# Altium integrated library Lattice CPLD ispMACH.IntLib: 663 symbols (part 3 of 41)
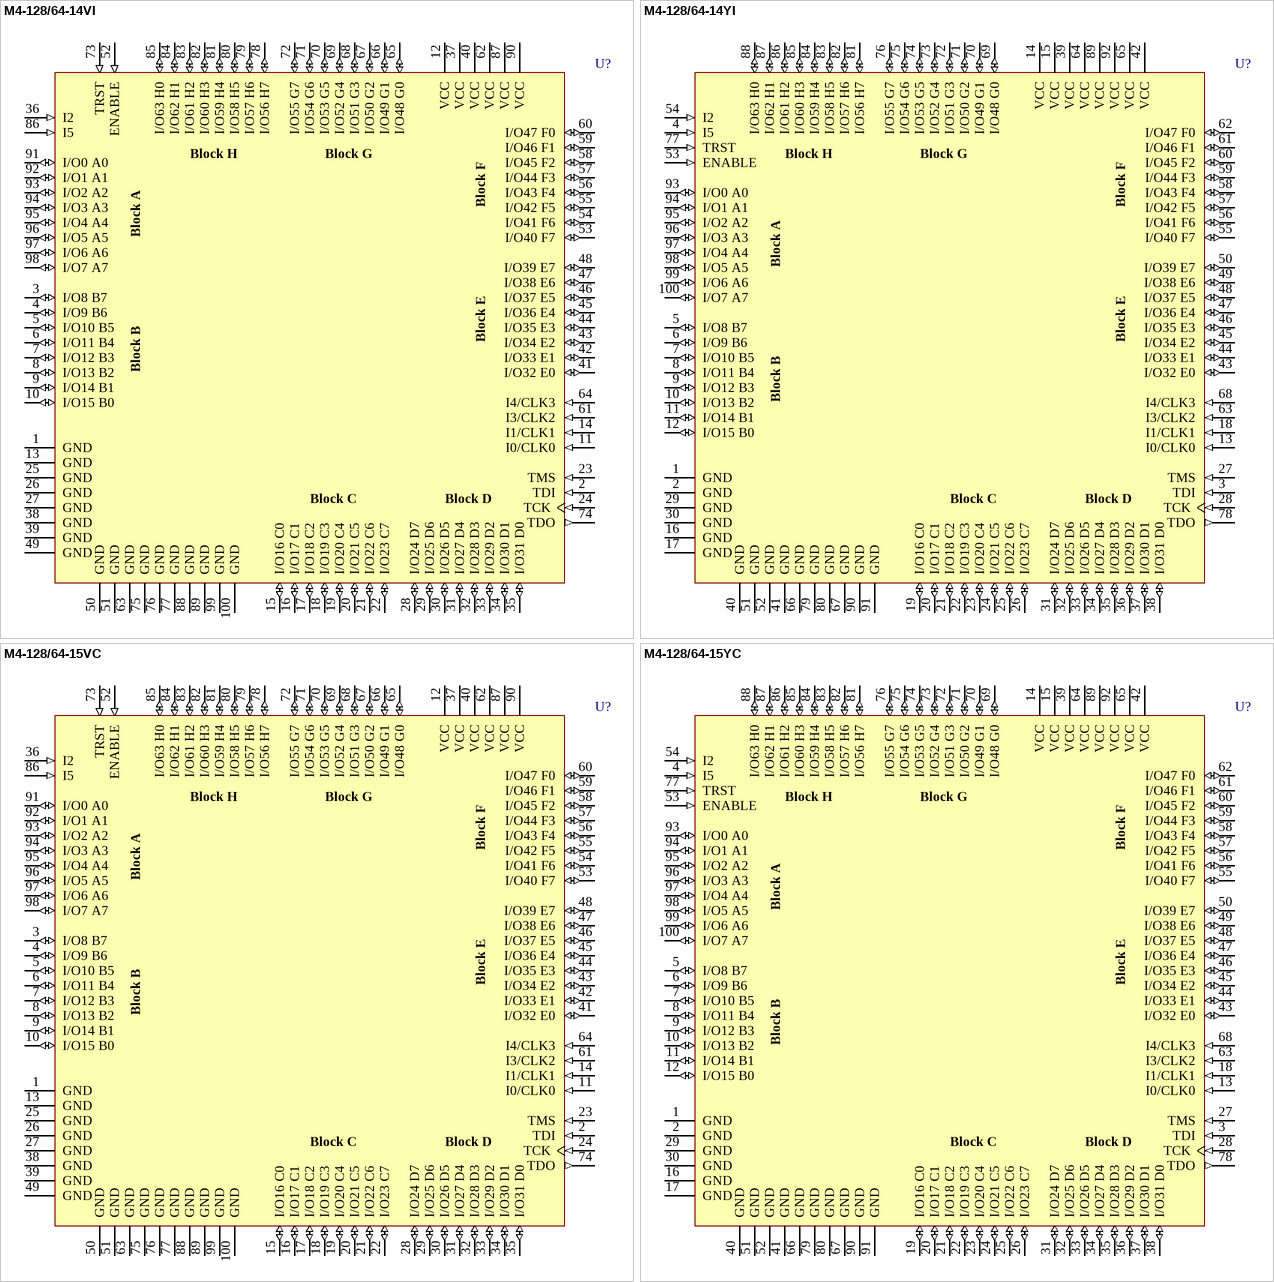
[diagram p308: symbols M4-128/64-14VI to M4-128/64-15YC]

## M4-128/64-15VC
designator U?
High-Performance EE CMOS In-System Programmable Logic
footprint TQFP100_N (Thin QFP, 100-Leads, Body 14x14mm, Pitch 0.5mm, IPC Medium Density)
footprint TQFP100_L (Thin QFP, 100-Leads, Body 14x14mm, Pitch 0.5mm, IPC High Density)
footprint TQFP100_M (Thin QFP, 100-Leads, Body 14x14mm, Pitch 0.5mm, IPC Low Density)
3D model M4-TQFP100 (100-Pin Thin Quad Flat Pack (TQFP100))
pins: 1 GND (power), 2 TDI (in), 3 I/O8 B7 (io), 4 I/O9 B6 (io), 5 I/O10 B5 (io), 6 I/O11 B4 (io), 7 I/O12 B3 (io), 8 I/O13 B2 (io), 9 I/O14 B1 (io), 10 I/O15 B0 (io), 11 I0/CLK0 (in), 12 VCC (power), 13 GND (power), 14 I1/CLK1 (in), 15 I/O16 C0 (io), 16 I/O17 C1 (io), 17 I/O18 C2 (io), 18 I/O19 C3 (io), 19 I/O20 C4 (io), 20 I/O21 C5 (io), 21 I/O22 C6 (io), 22 I/O23 C7 (io), 23 TMS (in), 24 TCK (in), 25 GND (power), 26 GND (power), 27 GND (power), 28 I/O24 D7 (io), 29 I/O25 D6 (io), 30 I/O26 D5 (io), 31 I/O27 D4 (io), 32 I/O28 D3 (io), 33 I/O29 D2 (io), 34 I/O30 D1 (io), 35 I/O31 D0 (io), 36 I2 (in), 37 VCC (power), 38 GND (power), 39 GND (power), 40 VCC (power), 41 I/O32 E0 (io), 42 I/O33 E1 (io), 43 I/O34 E2 (io), 44 I/O35 E3 (io), 45 I/O36 E4 (io), 46 I/O37 E5 (io), 47 I/O38 E6 (io), 48 I/O39 E7 (io), 49 GND (power), 50 GND (power), 51 GND (power), 52 ENABLE (in), 53 I/O40 F7 (io), 54 I/O41 F6 (io), 55 I/O42 F5 (io), 56 I/O43 F4 (io), 57 I/O44 F3 (io), 58 I/O45 F2 (io), 59 I/O46 F1 (io), 60 I/O47 F0 (io), 61 I3/CLK2 (in), 62 VCC (power), 63 GND (power), 64 I4/CLK3 (in), 65 I/O48 G0 (io), 66 I/O49 G1 (io), 67 I/O50 G2 (io), 68 I/O51 G3 (io), 69 I/O52 G4 (io), 70 I/O53 G5 (io), 71 I/O54 G6 (io), 72 I/O55 G7 (io), 73 TRST (in), 74 TDO (out), 75 GND (power), 76 GND (power), 77 GND (power), 78 I/O56 H7 (io), 79 I/O57 H6 (io), 80 I/O58 H5 (io), 81 I/O59 H4 (io), 82 I/O60 H3 (io), 83 I/O61 H2 (io), 84 I/O62 H1 (io), 85 I/O63 H0 (io), 86 I5 (in), 87 VCC (power), 88 GND (power), 89 GND (power), 90 VCC (power), 91 I/O0 A0 (io), 92 I/O1 A1 (io), 93 I/O2 A2 (io), 94 I/O3 A3 (io), 95 I/O4 A4 (io), 96 I/O5 A5 (io), 97 I/O6 A6 (io), 98 I/O7 A7 (io), 99 GND (power), 100 GND (power)

## M4-128/64-15YC
designator U?
High-Performance EE CMOS In-System Programmable Logic
footprint PQFP100_N (QFP, 100-Leads, Body 20x14mm, Pitch 0.65mm, IPC Medium Density)
footprint PQFP100_L (QFP, 100-Leads, Body 20x14mm, Pitch 0.65mm, IPC High Density)
footprint PQFP100_M (QFP, 100-Leads, Body 20x14mm, Pitch 0.65mm, IPC Low Density)
3D model PQFP-100 (100-Pin Quad Flat Pack Rectangular 0.65 mm Pitch)
pins: 1 GND (power), 2 GND (power), 3 TDI (in), 4 I5 (in), 5 I/O8 B7 (io), 6 I/O9 B6 (io), 7 I/O10 B5 (io), 8 I/O11 B4 (io), 9 I/O12 B3 (io), 10 I/O13 B2 (io), 11 I/O14 B1 (io), 12 I/O15 B0 (io), 13 I0/CLK0 (in), 14 VCC (power), 15 VCC (power), 16 GND (power), 17 GND (power), 18 I1/CLK1 (in), 19 I/O16 C0 (io), 20 I/O17 C1 (io), 21 I/O18 C2 (io), 22 I/O19 C3 (io), 23 I/O20 C4 (io), 24 I/O21 C5 (io), 25 I/O22 C6 (io), 26 I/O23 C7 (io), 27 TMS (in), 28 TCK (in), 29 GND (power), 30 GND (power), 31 I/O24 D7 (io), 32 I/O25 D6 (io), 33 I/O26 D5 (io), 34 I/O27 D4 (io), 35 I/O28 D3 (io), 36 I/O29 D2 (io), 37 I/O30 D1 (io), 38 I/O31 D0 (io), 39 VCC (power), 40 GND (power), 41 GND (power), 42 VCC (power), 43 I/O32 E0 (io), 44 I/O33 E1 (io), 45 I/O34 E2 (io), 46 I/O35 E3 (io), 47 I/O36 E4 (io), 48 I/O37 E5 (io), 49 I/O38 E6 (io), 50 I/O39 E7 (io), 51 GND (power), 52 GND (power), 53 ENABLE (in), 54 I2 (in), 55 I/O40 F7 (io), 56 I/O41 F6 (io), 57 I/O42 F5 (io), 58 I/O43 F4 (io), 59 I/O44 F3 (io), 60 I/O45 F2 (io), 61 I/O46 F1 (io), 62 I/O47 F0 (io), 63 I3/CLK2 (in), 64 VCC (power), 65 VCC (power), 66 GND (power), 67 GND (power), 68 I4/CLK3 (in), 69 I/O48 G0 (io), 70 I/O49 G1 (io), 71 I/O50 G2 (io), 72 I/O51 G3 (io), 73 I/O52 G4 (io), 74 I/O53 G5 (io), 75 I/O54 G6 (io), 76 I/O55 G7 (io), 77 TRST (in), 78 TDO (out), 79 GND (power), 80 GND (power), 81 I/O56 H7 (io), 82 I/O57 H6 (io), 83 I/O58 H5 (io), 84 I/O59 H4 (io), 85 I/O60 H3 (io), 86 I/O61 H2 (io), 87 I/O62 H1 (io), 88 I/O63 H0 (io), 89 VCC (power), 90 GND (power), 91 GND (power), 92 VCC (power), 93 I/O0 A0 (io), 94 I/O1 A1 (io), 95 I/O2 A2 (io), 96 I/O3 A3 (io), 97 I/O4 A4 (io), 98 I/O5 A5 (io), 99 I/O6 A6 (io), 100 I/O7 A7 (io)

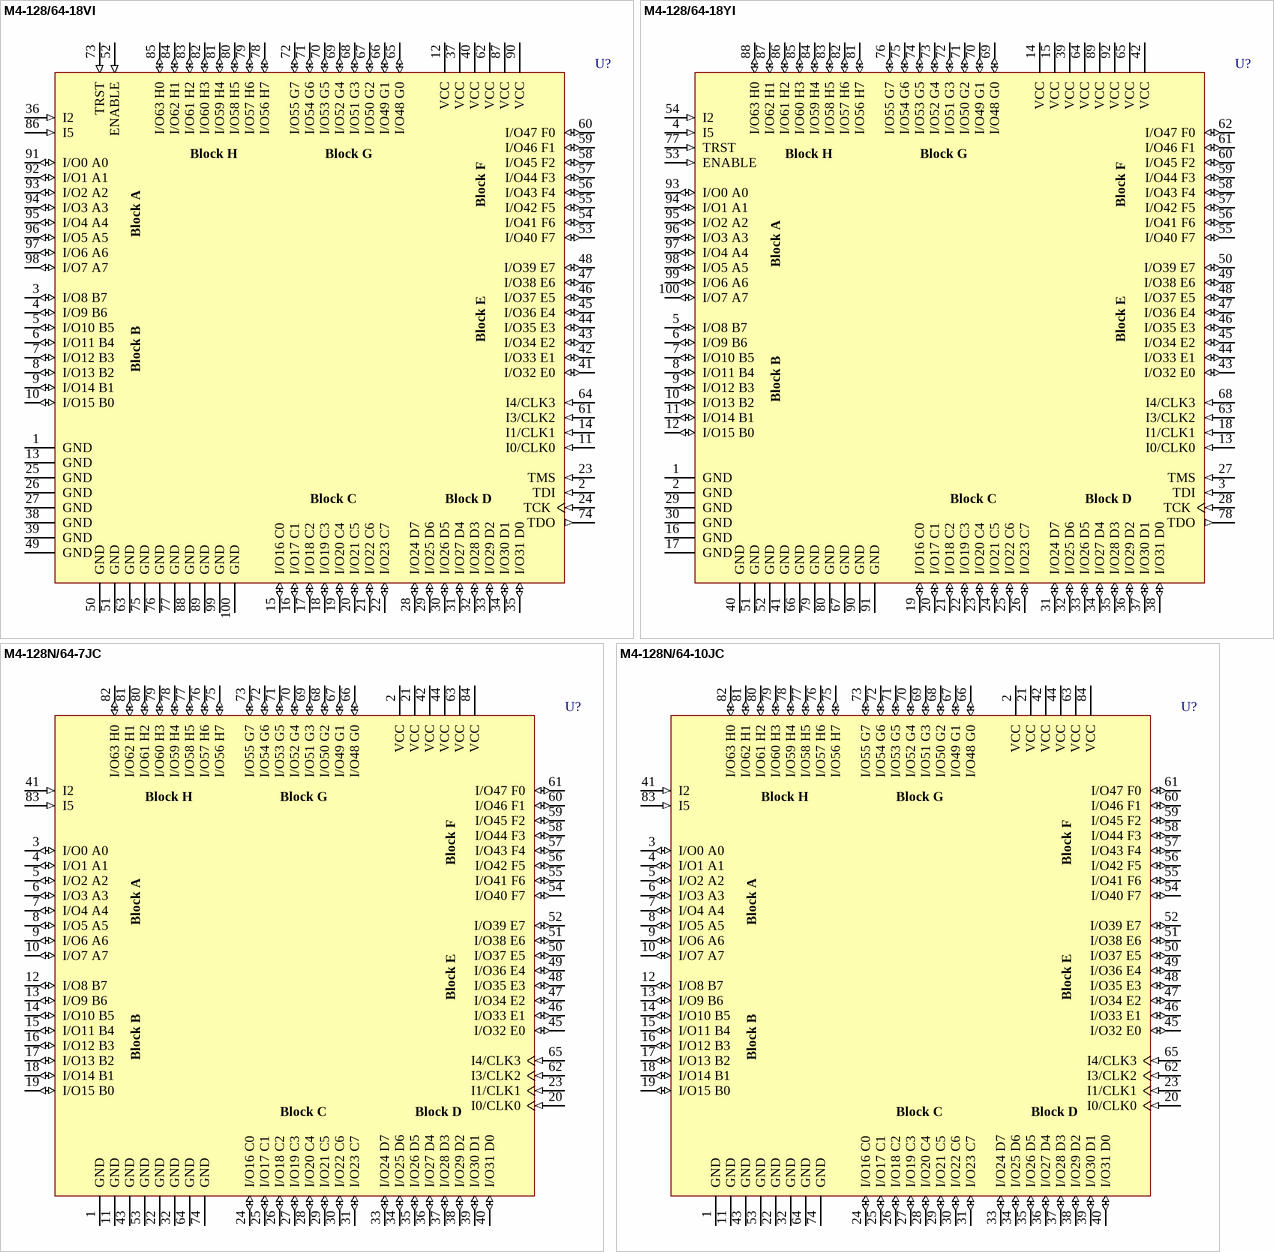
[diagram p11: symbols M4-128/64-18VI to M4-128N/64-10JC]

## M4-128/64-18VI
designator U?
High-Performance EE CMOS In-System Programmable Logic
footprint TQFP100_N (Thin QFP, 100-Leads, Body 14x14mm, Pitch 0.5mm, IPC Medium Density)
footprint TQFP100_L (Thin QFP, 100-Leads, Body 14x14mm, Pitch 0.5mm, IPC High Density)
footprint TQFP100_M (Thin QFP, 100-Leads, Body 14x14mm, Pitch 0.5mm, IPC Low Density)
3D model M4-TQFP100 (100-Pin Thin Quad Flat Pack (TQFP100))
pins: 1 GND (power), 2 TDI (in), 3 I/O8 B7 (io), 4 I/O9 B6 (io), 5 I/O10 B5 (io), 6 I/O11 B4 (io), 7 I/O12 B3 (io), 8 I/O13 B2 (io), 9 I/O14 B1 (io), 10 I/O15 B0 (io), 11 I0/CLK0 (in), 12 VCC (power), 13 GND (power), 14 I1/CLK1 (in), 15 I/O16 C0 (io), 16 I/O17 C1 (io), 17 I/O18 C2 (io), 18 I/O19 C3 (io), 19 I/O20 C4 (io), 20 I/O21 C5 (io), 21 I/O22 C6 (io), 22 I/O23 C7 (io), 23 TMS (in), 24 TCK (in), 25 GND (power), 26 GND (power), 27 GND (power), 28 I/O24 D7 (io), 29 I/O25 D6 (io), 30 I/O26 D5 (io), 31 I/O27 D4 (io), 32 I/O28 D3 (io), 33 I/O29 D2 (io), 34 I/O30 D1 (io), 35 I/O31 D0 (io), 36 I2 (in), 37 VCC (power), 38 GND (power), 39 GND (power), 40 VCC (power), 41 I/O32 E0 (io), 42 I/O33 E1 (io), 43 I/O34 E2 (io), 44 I/O35 E3 (io), 45 I/O36 E4 (io), 46 I/O37 E5 (io), 47 I/O38 E6 (io), 48 I/O39 E7 (io), 49 GND (power), 50 GND (power), 51 GND (power), 52 ENABLE (in), 53 I/O40 F7 (io), 54 I/O41 F6 (io), 55 I/O42 F5 (io), 56 I/O43 F4 (io), 57 I/O44 F3 (io), 58 I/O45 F2 (io), 59 I/O46 F1 (io), 60 I/O47 F0 (io), 61 I3/CLK2 (in), 62 VCC (power), 63 GND (power), 64 I4/CLK3 (in), 65 I/O48 G0 (io), 66 I/O49 G1 (io), 67 I/O50 G2 (io), 68 I/O51 G3 (io), 69 I/O52 G4 (io), 70 I/O53 G5 (io), 71 I/O54 G6 (io), 72 I/O55 G7 (io), 73 TRST (in), 74 TDO (out), 75 GND (power), 76 GND (power), 77 GND (power), 78 I/O56 H7 (io), 79 I/O57 H6 (io), 80 I/O58 H5 (io), 81 I/O59 H4 (io), 82 I/O60 H3 (io), 83 I/O61 H2 (io), 84 I/O62 H1 (io), 85 I/O63 H0 (io), 86 I5 (in), 87 VCC (power), 88 GND (power), 89 GND (power), 90 VCC (power), 91 I/O0 A0 (io), 92 I/O1 A1 (io), 93 I/O2 A2 (io), 94 I/O3 A3 (io), 95 I/O4 A4 (io), 96 I/O5 A5 (io), 97 I/O6 A6 (io), 98 I/O7 A7 (io), 99 GND (power), 100 GND (power)

## M4-128/64-18YI
designator U?
High-Performance EE CMOS In-System Programmable Logic
footprint PQFP100_N (QFP, 100-Leads, Body 20x14mm, Pitch 0.65mm, IPC Medium Density)
footprint PQFP100_L (QFP, 100-Leads, Body 20x14mm, Pitch 0.65mm, IPC High Density)
footprint PQFP100_M (QFP, 100-Leads, Body 20x14mm, Pitch 0.65mm, IPC Low Density)
3D model PQFP-100 (100-Pin Quad Flat Pack Rectangular 0.65 mm Pitch)
pins: 1 GND (power), 2 GND (power), 3 TDI (in), 4 I5 (in), 5 I/O8 B7 (io), 6 I/O9 B6 (io), 7 I/O10 B5 (io), 8 I/O11 B4 (io), 9 I/O12 B3 (io), 10 I/O13 B2 (io), 11 I/O14 B1 (io), 12 I/O15 B0 (io), 13 I0/CLK0 (in), 14 VCC (power), 15 VCC (power), 16 GND (power), 17 GND (power), 18 I1/CLK1 (in), 19 I/O16 C0 (io), 20 I/O17 C1 (io), 21 I/O18 C2 (io), 22 I/O19 C3 (io), 23 I/O20 C4 (io), 24 I/O21 C5 (io), 25 I/O22 C6 (io), 26 I/O23 C7 (io), 27 TMS (in), 28 TCK (in), 29 GND (power), 30 GND (power), 31 I/O24 D7 (io), 32 I/O25 D6 (io), 33 I/O26 D5 (io), 34 I/O27 D4 (io), 35 I/O28 D3 (io), 36 I/O29 D2 (io), 37 I/O30 D1 (io), 38 I/O31 D0 (io), 39 VCC (power), 40 GND (power), 41 GND (power), 42 VCC (power), 43 I/O32 E0 (io), 44 I/O33 E1 (io), 45 I/O34 E2 (io), 46 I/O35 E3 (io), 47 I/O36 E4 (io), 48 I/O37 E5 (io), 49 I/O38 E6 (io), 50 I/O39 E7 (io), 51 GND (power), 52 GND (power), 53 ENABLE (in), 54 I2 (in), 55 I/O40 F7 (io), 56 I/O41 F6 (io), 57 I/O42 F5 (io), 58 I/O43 F4 (io), 59 I/O44 F3 (io), 60 I/O45 F2 (io), 61 I/O46 F1 (io), 62 I/O47 F0 (io), 63 I3/CLK2 (in), 64 VCC (power), 65 VCC (power), 66 GND (power), 67 GND (power), 68 I4/CLK3 (in), 69 I/O48 G0 (io), 70 I/O49 G1 (io), 71 I/O50 G2 (io), 72 I/O51 G3 (io), 73 I/O52 G4 (io), 74 I/O53 G5 (io), 75 I/O54 G6 (io), 76 I/O55 G7 (io), 77 TRST (in), 78 TDO (out), 79 GND (power), 80 GND (power), 81 I/O56 H7 (io), 82 I/O57 H6 (io), 83 I/O58 H5 (io), 84 I/O59 H4 (io), 85 I/O60 H3 (io), 86 I/O61 H2 (io), 87 I/O62 H1 (io), 88 I/O63 H0 (io), 89 VCC (power), 90 GND (power), 91 GND (power), 92 VCC (power), 93 I/O0 A0 (io), 94 I/O1 A1 (io), 95 I/O2 A2 (io), 96 I/O3 A3 (io), 97 I/O4 A4 (io), 98 I/O5 A5 (io), 99 I/O6 A6 (io), 100 I/O7 A7 (io)

## M4-128N/64-7JC
designator U?
High-Performance EE CMOS In-System Programmable Logic
footprint PLCC84_N (Leaded Chip Carrier, 84-Leads, Body 29.3x29.3mm, Pitch 1.27mm, IPC Medium Density)
footprint PLCC84_L (Leaded Chip Carrier, 84-Leads, Body 29.3x29.3mm, Pitch 1.27mm, IPC High Density)
footprint PLCC84_M (Leaded Chip Carrier, 84-Leads, Body 29.3x29.3mm, Pitch 1.27mm, IPC Low Density)
3D model M4-PLCC84 (84-Pin Leaded Chip Carrier 1.27 mm Pitch)
pins: 1 GND (power), 2 VCC (power), 3 I/O0 A0 (io), 4 I/O1 A1 (io), 5 I/O2 A2 (io), 6 I/O3 A3 (io), 7 I/O4 A4 (io), 8 I/O5 A5 (io), 9 I/O6 A6 (io), 10 I/O7 A7 (io), 11 GND (power), 12 I/O8 B7 (io), 13 I/O9 B6 (io), 14 I/O10 B5 (io), 15 I/O11 B4 (io), 16 I/O12 B3 (io), 17 I/O13 B2 (io), 18 I/O14 B1 (io), 19 I/O15 B0 (io), 20 I0/CLK0 (in), 21 VCC (power), 22 GND (power), 23 I1/CLK1 (in), 24 I/O16 C0 (io), 25 I/O17 C1 (io), 26 I/O18 C2 (io), 27 I/O19 C3 (io), 28 I/O20 C4 (io), 29 I/O21 C5 (io), 30 I/O22 C6 (io), 31 I/O23 C7 (io), 32 GND (power), 33 I/O24 D7 (io), 34 I/O25 D6 (io), 35 I/O26 D5 (io), 36 I/O27 D4 (io), 37 I/O28 D3 (io), 38 I/O29 D2 (io), 39 I/O30 D1 (io), 40 I/O31 D0 (io), 41 I2 (in), 42 VCC (power), 43 GND (power), 44 VCC (power), 45 I/O32 E0 (io), 46 I/O33 E1 (io), 47 I/O34 E2 (io), 48 I/O35 E3 (io), 49 I/O36 E4 (io), 50 I/O37 E5 (io), 51 I/O38 E6 (io), 52 I/O39 E7 (io), 53 GND (power), 54 I/O40 F7 (io), 55 I/O41 F6 (io), 56 I/O42 F5 (io), 57 I/O43 F4 (io), 58 I/O44 F3 (io), 59 I/O45 F2 (io), 60 I/O46 F1 (io), 61 I/O47 F0 (io), 62 I3/CLK2 (in), 63 VCC (power), 64 GND (power), 65 I4/CLK3 (in), 66 I/O48 G0 (io), 67 I/O49 G1 (io), 68 I/O50 G2 (io), 69 I/O51 G3 (io), 70 I/O52 G4 (io), 71 I/O53 G5 (io), 72 I/O54 G6 (io), 73 I/O55 G7 (io), 74 GND (power), 75 I/O56 H7 (io), 76 I/O57 H6 (io), 77 I/O58 H5 (io), 78 I/O59 H4 (io), 79 I/O60 H3 (io), 80 I/O61 H2 (io), 81 I/O62 H1 (io), 82 I/O63 H0 (io), 83 I5 (in), 84 VCC (power)

## M4-128N/64-10JC
designator U?
High-Performance EE CMOS In-System Programmable Logic
footprint PLCC84_N (Leaded Chip Carrier, 84-Leads, Body 29.3x29.3mm, Pitch 1.27mm, IPC Medium Density)
footprint PLCC84_L (Leaded Chip Carrier, 84-Leads, Body 29.3x29.3mm, Pitch 1.27mm, IPC High Density)
footprint PLCC84_M (Leaded Chip Carrier, 84-Leads, Body 29.3x29.3mm, Pitch 1.27mm, IPC Low Density)
3D model M4-PLCC84 (84-Pin Leaded Chip Carrier 1.27 mm Pitch)
pins: 1 GND (power), 2 VCC (power), 3 I/O0 A0 (io), 4 I/O1 A1 (io), 5 I/O2 A2 (io), 6 I/O3 A3 (io), 7 I/O4 A4 (io), 8 I/O5 A5 (io), 9 I/O6 A6 (io), 10 I/O7 A7 (io), 11 GND (power), 12 I/O8 B7 (io), 13 I/O9 B6 (io), 14 I/O10 B5 (io), 15 I/O11 B4 (io), 16 I/O12 B3 (io), 17 I/O13 B2 (io), 18 I/O14 B1 (io), 19 I/O15 B0 (io), 20 I0/CLK0 (in), 21 VCC (power), 22 GND (power), 23 I1/CLK1 (in), 24 I/O16 C0 (io), 25 I/O17 C1 (io), 26 I/O18 C2 (io), 27 I/O19 C3 (io), 28 I/O20 C4 (io), 29 I/O21 C5 (io), 30 I/O22 C6 (io), 31 I/O23 C7 (io), 32 GND (power), 33 I/O24 D7 (io), 34 I/O25 D6 (io), 35 I/O26 D5 (io), 36 I/O27 D4 (io), 37 I/O28 D3 (io), 38 I/O29 D2 (io), 39 I/O30 D1 (io), 40 I/O31 D0 (io), 41 I2 (in), 42 VCC (power), 43 GND (power), 44 VCC (power), 45 I/O32 E0 (io), 46 I/O33 E1 (io), 47 I/O34 E2 (io), 48 I/O35 E3 (io), 49 I/O36 E4 (io), 50 I/O37 E5 (io), 51 I/O38 E6 (io), 52 I/O39 E7 (io), 53 GND (power), 54 I/O40 F7 (io), 55 I/O41 F6 (io), 56 I/O42 F5 (io), 57 I/O43 F4 (io), 58 I/O44 F3 (io), 59 I/O45 F2 (io), 60 I/O46 F1 (io), 61 I/O47 F0 (io), 62 I3/CLK2 (in), 63 VCC (power), 64 GND (power), 65 I4/CLK3 (in), 66 I/O48 G0 (io), 67 I/O49 G1 (io), 68 I/O50 G2 (io), 69 I/O51 G3 (io), 70 I/O52 G4 (io), 71 I/O53 G5 (io), 72 I/O54 G6 (io), 73 I/O55 G7 (io), 74 GND (power), 75 I/O56 H7 (io), 76 I/O57 H6 (io), 77 I/O58 H5 (io), 78 I/O59 H4 (io), 79 I/O60 H3 (io), 80 I/O61 H2 (io), 81 I/O62 H1 (io), 82 I/O63 H0 (io), 83 I5 (in), 84 VCC (power)

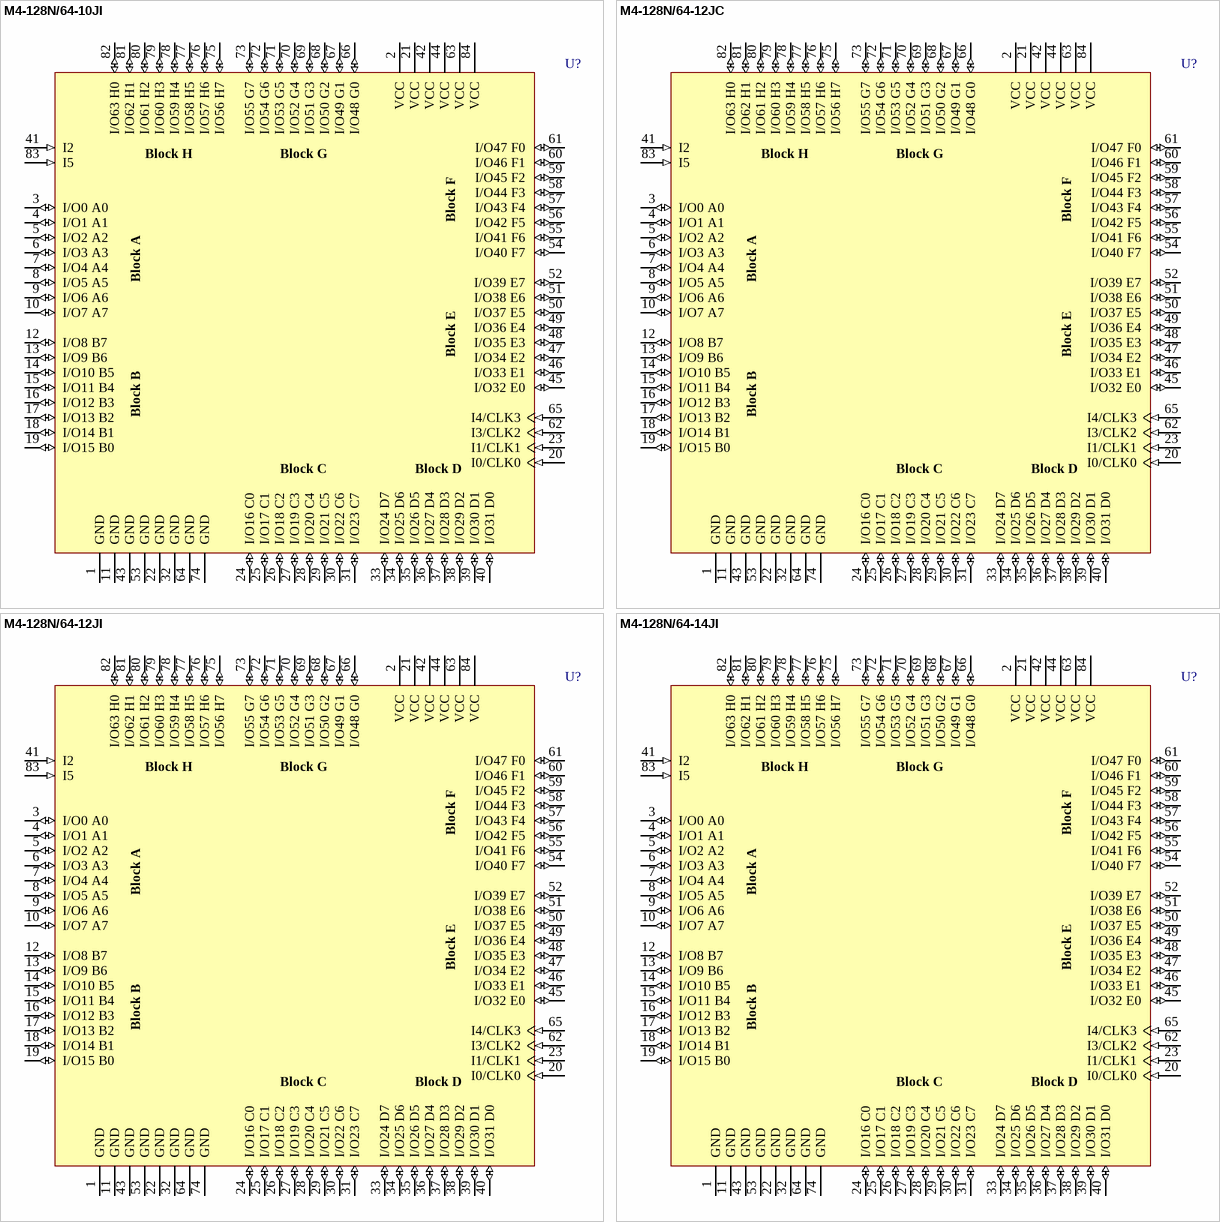
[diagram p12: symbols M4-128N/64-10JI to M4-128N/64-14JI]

## M4-128N/64-10JI
designator U?
High-Performance EE CMOS In-System Programmable Logic
footprint PLCC84_N (Leaded Chip Carrier, 84-Leads, Body 29.3x29.3mm, Pitch 1.27mm, IPC Medium Density)
footprint PLCC84_L (Leaded Chip Carrier, 84-Leads, Body 29.3x29.3mm, Pitch 1.27mm, IPC High Density)
footprint PLCC84_M (Leaded Chip Carrier, 84-Leads, Body 29.3x29.3mm, Pitch 1.27mm, IPC Low Density)
3D model M4-PLCC84 (84-Pin Leaded Chip Carrier 1.27 mm Pitch)
pins: 1 GND (power), 2 VCC (power), 3 I/O0 A0 (io), 4 I/O1 A1 (io), 5 I/O2 A2 (io), 6 I/O3 A3 (io), 7 I/O4 A4 (io), 8 I/O5 A5 (io), 9 I/O6 A6 (io), 10 I/O7 A7 (io), 11 GND (power), 12 I/O8 B7 (io), 13 I/O9 B6 (io), 14 I/O10 B5 (io), 15 I/O11 B4 (io), 16 I/O12 B3 (io), 17 I/O13 B2 (io), 18 I/O14 B1 (io), 19 I/O15 B0 (io), 20 I0/CLK0 (in), 21 VCC (power), 22 GND (power), 23 I1/CLK1 (in), 24 I/O16 C0 (io), 25 I/O17 C1 (io), 26 I/O18 C2 (io), 27 I/O19 C3 (io), 28 I/O20 C4 (io), 29 I/O21 C5 (io), 30 I/O22 C6 (io), 31 I/O23 C7 (io), 32 GND (power), 33 I/O24 D7 (io), 34 I/O25 D6 (io), 35 I/O26 D5 (io), 36 I/O27 D4 (io), 37 I/O28 D3 (io), 38 I/O29 D2 (io), 39 I/O30 D1 (io), 40 I/O31 D0 (io), 41 I2 (in), 42 VCC (power), 43 GND (power), 44 VCC (power), 45 I/O32 E0 (io), 46 I/O33 E1 (io), 47 I/O34 E2 (io), 48 I/O35 E3 (io), 49 I/O36 E4 (io), 50 I/O37 E5 (io), 51 I/O38 E6 (io), 52 I/O39 E7 (io), 53 GND (power), 54 I/O40 F7 (io), 55 I/O41 F6 (io), 56 I/O42 F5 (io), 57 I/O43 F4 (io), 58 I/O44 F3 (io), 59 I/O45 F2 (io), 60 I/O46 F1 (io), 61 I/O47 F0 (io), 62 I3/CLK2 (in), 63 VCC (power), 64 GND (power), 65 I4/CLK3 (in), 66 I/O48 G0 (io), 67 I/O49 G1 (io), 68 I/O50 G2 (io), 69 I/O51 G3 (io), 70 I/O52 G4 (io), 71 I/O53 G5 (io), 72 I/O54 G6 (io), 73 I/O55 G7 (io), 74 GND (power), 75 I/O56 H7 (io), 76 I/O57 H6 (io), 77 I/O58 H5 (io), 78 I/O59 H4 (io), 79 I/O60 H3 (io), 80 I/O61 H2 (io), 81 I/O62 H1 (io), 82 I/O63 H0 (io), 83 I5 (in), 84 VCC (power)

## M4-128N/64-12JC
designator U?
High-Performance EE CMOS In-System Programmable Logic
footprint PLCC84_N (Leaded Chip Carrier, 84-Leads, Body 29.3x29.3mm, Pitch 1.27mm, IPC Medium Density)
footprint PLCC84_L (Leaded Chip Carrier, 84-Leads, Body 29.3x29.3mm, Pitch 1.27mm, IPC High Density)
footprint PLCC84_M (Leaded Chip Carrier, 84-Leads, Body 29.3x29.3mm, Pitch 1.27mm, IPC Low Density)
3D model M4-PLCC84 (84-Pin Leaded Chip Carrier 1.27 mm Pitch)
pins: 1 GND (power), 2 VCC (power), 3 I/O0 A0 (io), 4 I/O1 A1 (io), 5 I/O2 A2 (io), 6 I/O3 A3 (io), 7 I/O4 A4 (io), 8 I/O5 A5 (io), 9 I/O6 A6 (io), 10 I/O7 A7 (io), 11 GND (power), 12 I/O8 B7 (io), 13 I/O9 B6 (io), 14 I/O10 B5 (io), 15 I/O11 B4 (io), 16 I/O12 B3 (io), 17 I/O13 B2 (io), 18 I/O14 B1 (io), 19 I/O15 B0 (io), 20 I0/CLK0 (in), 21 VCC (power), 22 GND (power), 23 I1/CLK1 (in), 24 I/O16 C0 (io), 25 I/O17 C1 (io), 26 I/O18 C2 (io), 27 I/O19 C3 (io), 28 I/O20 C4 (io), 29 I/O21 C5 (io), 30 I/O22 C6 (io), 31 I/O23 C7 (io), 32 GND (power), 33 I/O24 D7 (io), 34 I/O25 D6 (io), 35 I/O26 D5 (io), 36 I/O27 D4 (io), 37 I/O28 D3 (io), 38 I/O29 D2 (io), 39 I/O30 D1 (io), 40 I/O31 D0 (io), 41 I2 (in), 42 VCC (power), 43 GND (power), 44 VCC (power), 45 I/O32 E0 (io), 46 I/O33 E1 (io), 47 I/O34 E2 (io), 48 I/O35 E3 (io), 49 I/O36 E4 (io), 50 I/O37 E5 (io), 51 I/O38 E6 (io), 52 I/O39 E7 (io), 53 GND (power), 54 I/O40 F7 (io), 55 I/O41 F6 (io), 56 I/O42 F5 (io), 57 I/O43 F4 (io), 58 I/O44 F3 (io), 59 I/O45 F2 (io), 60 I/O46 F1 (io), 61 I/O47 F0 (io), 62 I3/CLK2 (in), 63 VCC (power), 64 GND (power), 65 I4/CLK3 (in), 66 I/O48 G0 (io), 67 I/O49 G1 (io), 68 I/O50 G2 (io), 69 I/O51 G3 (io), 70 I/O52 G4 (io), 71 I/O53 G5 (io), 72 I/O54 G6 (io), 73 I/O55 G7 (io), 74 GND (power), 75 I/O56 H7 (io), 76 I/O57 H6 (io), 77 I/O58 H5 (io), 78 I/O59 H4 (io), 79 I/O60 H3 (io), 80 I/O61 H2 (io), 81 I/O62 H1 (io), 82 I/O63 H0 (io), 83 I5 (in), 84 VCC (power)

## M4-128N/64-12JI
designator U?
High-Performance EE CMOS In-System Programmable Logic
footprint PLCC84_N (Leaded Chip Carrier, 84-Leads, Body 29.3x29.3mm, Pitch 1.27mm, IPC Medium Density)
footprint PLCC84_L (Leaded Chip Carrier, 84-Leads, Body 29.3x29.3mm, Pitch 1.27mm, IPC High Density)
footprint PLCC84_M (Leaded Chip Carrier, 84-Leads, Body 29.3x29.3mm, Pitch 1.27mm, IPC Low Density)
3D model M4-PLCC84 (84-Pin Leaded Chip Carrier 1.27 mm Pitch)
pins: 1 GND (power), 2 VCC (power), 3 I/O0 A0 (io), 4 I/O1 A1 (io), 5 I/O2 A2 (io), 6 I/O3 A3 (io), 7 I/O4 A4 (io), 8 I/O5 A5 (io), 9 I/O6 A6 (io), 10 I/O7 A7 (io), 11 GND (power), 12 I/O8 B7 (io), 13 I/O9 B6 (io), 14 I/O10 B5 (io), 15 I/O11 B4 (io), 16 I/O12 B3 (io), 17 I/O13 B2 (io), 18 I/O14 B1 (io), 19 I/O15 B0 (io), 20 I0/CLK0 (in), 21 VCC (power), 22 GND (power), 23 I1/CLK1 (in), 24 I/O16 C0 (io), 25 I/O17 C1 (io), 26 I/O18 C2 (io), 27 I/O19 C3 (io), 28 I/O20 C4 (io), 29 I/O21 C5 (io), 30 I/O22 C6 (io), 31 I/O23 C7 (io), 32 GND (power), 33 I/O24 D7 (io), 34 I/O25 D6 (io), 35 I/O26 D5 (io), 36 I/O27 D4 (io), 37 I/O28 D3 (io), 38 I/O29 D2 (io), 39 I/O30 D1 (io), 40 I/O31 D0 (io), 41 I2 (in), 42 VCC (power), 43 GND (power), 44 VCC (power), 45 I/O32 E0 (io), 46 I/O33 E1 (io), 47 I/O34 E2 (io), 48 I/O35 E3 (io), 49 I/O36 E4 (io), 50 I/O37 E5 (io), 51 I/O38 E6 (io), 52 I/O39 E7 (io), 53 GND (power), 54 I/O40 F7 (io), 55 I/O41 F6 (io), 56 I/O42 F5 (io), 57 I/O43 F4 (io), 58 I/O44 F3 (io), 59 I/O45 F2 (io), 60 I/O46 F1 (io), 61 I/O47 F0 (io), 62 I3/CLK2 (in), 63 VCC (power), 64 GND (power), 65 I4/CLK3 (in), 66 I/O48 G0 (io), 67 I/O49 G1 (io), 68 I/O50 G2 (io), 69 I/O51 G3 (io), 70 I/O52 G4 (io), 71 I/O53 G5 (io), 72 I/O54 G6 (io), 73 I/O55 G7 (io), 74 GND (power), 75 I/O56 H7 (io), 76 I/O57 H6 (io), 77 I/O58 H5 (io), 78 I/O59 H4 (io), 79 I/O60 H3 (io), 80 I/O61 H2 (io), 81 I/O62 H1 (io), 82 I/O63 H0 (io), 83 I5 (in), 84 VCC (power)

## M4-128N/64-14JI
designator U?
High-Performance EE CMOS In-System Programmable Logic
footprint PLCC84_N (Leaded Chip Carrier, 84-Leads, Body 29.3x29.3mm, Pitch 1.27mm, IPC Medium Density)
footprint PLCC84_L (Leaded Chip Carrier, 84-Leads, Body 29.3x29.3mm, Pitch 1.27mm, IPC High Density)
footprint PLCC84_M (Leaded Chip Carrier, 84-Leads, Body 29.3x29.3mm, Pitch 1.27mm, IPC Low Density)
3D model M4-PLCC84 (84-Pin Leaded Chip Carrier 1.27 mm Pitch)
pins: 1 GND (power), 2 VCC (power), 3 I/O0 A0 (io), 4 I/O1 A1 (io), 5 I/O2 A2 (io), 6 I/O3 A3 (io), 7 I/O4 A4 (io), 8 I/O5 A5 (io), 9 I/O6 A6 (io), 10 I/O7 A7 (io), 11 GND (power), 12 I/O8 B7 (io), 13 I/O9 B6 (io), 14 I/O10 B5 (io), 15 I/O11 B4 (io), 16 I/O12 B3 (io), 17 I/O13 B2 (io), 18 I/O14 B1 (io), 19 I/O15 B0 (io), 20 I0/CLK0 (in), 21 VCC (power), 22 GND (power), 23 I1/CLK1 (in), 24 I/O16 C0 (io), 25 I/O17 C1 (io), 26 I/O18 C2 (io), 27 I/O19 C3 (io), 28 I/O20 C4 (io), 29 I/O21 C5 (io), 30 I/O22 C6 (io), 31 I/O23 C7 (io), 32 GND (power), 33 I/O24 D7 (io), 34 I/O25 D6 (io), 35 I/O26 D5 (io), 36 I/O27 D4 (io), 37 I/O28 D3 (io), 38 I/O29 D2 (io), 39 I/O30 D1 (io), 40 I/O31 D0 (io), 41 I2 (in), 42 VCC (power), 43 GND (power), 44 VCC (power), 45 I/O32 E0 (io), 46 I/O33 E1 (io), 47 I/O34 E2 (io), 48 I/O35 E3 (io), 49 I/O36 E4 (io), 50 I/O37 E5 (io), 51 I/O38 E6 (io), 52 I/O39 E7 (io), 53 GND (power), 54 I/O40 F7 (io), 55 I/O41 F6 (io), 56 I/O42 F5 (io), 57 I/O43 F4 (io), 58 I/O44 F3 (io), 59 I/O45 F2 (io), 60 I/O46 F1 (io), 61 I/O47 F0 (io), 62 I3/CLK2 (in), 63 VCC (power), 64 GND (power), 65 I4/CLK3 (in), 66 I/O48 G0 (io), 67 I/O49 G1 (io), 68 I/O50 G2 (io), 69 I/O51 G3 (io), 70 I/O52 G4 (io), 71 I/O53 G5 (io), 72 I/O54 G6 (io), 73 I/O55 G7 (io), 74 GND (power), 75 I/O56 H7 (io), 76 I/O57 H6 (io), 77 I/O58 H5 (io), 78 I/O59 H4 (io), 79 I/O60 H3 (io), 80 I/O61 H2 (io), 81 I/O62 H1 (io), 82 I/O63 H0 (io), 83 I5 (in), 84 VCC (power)

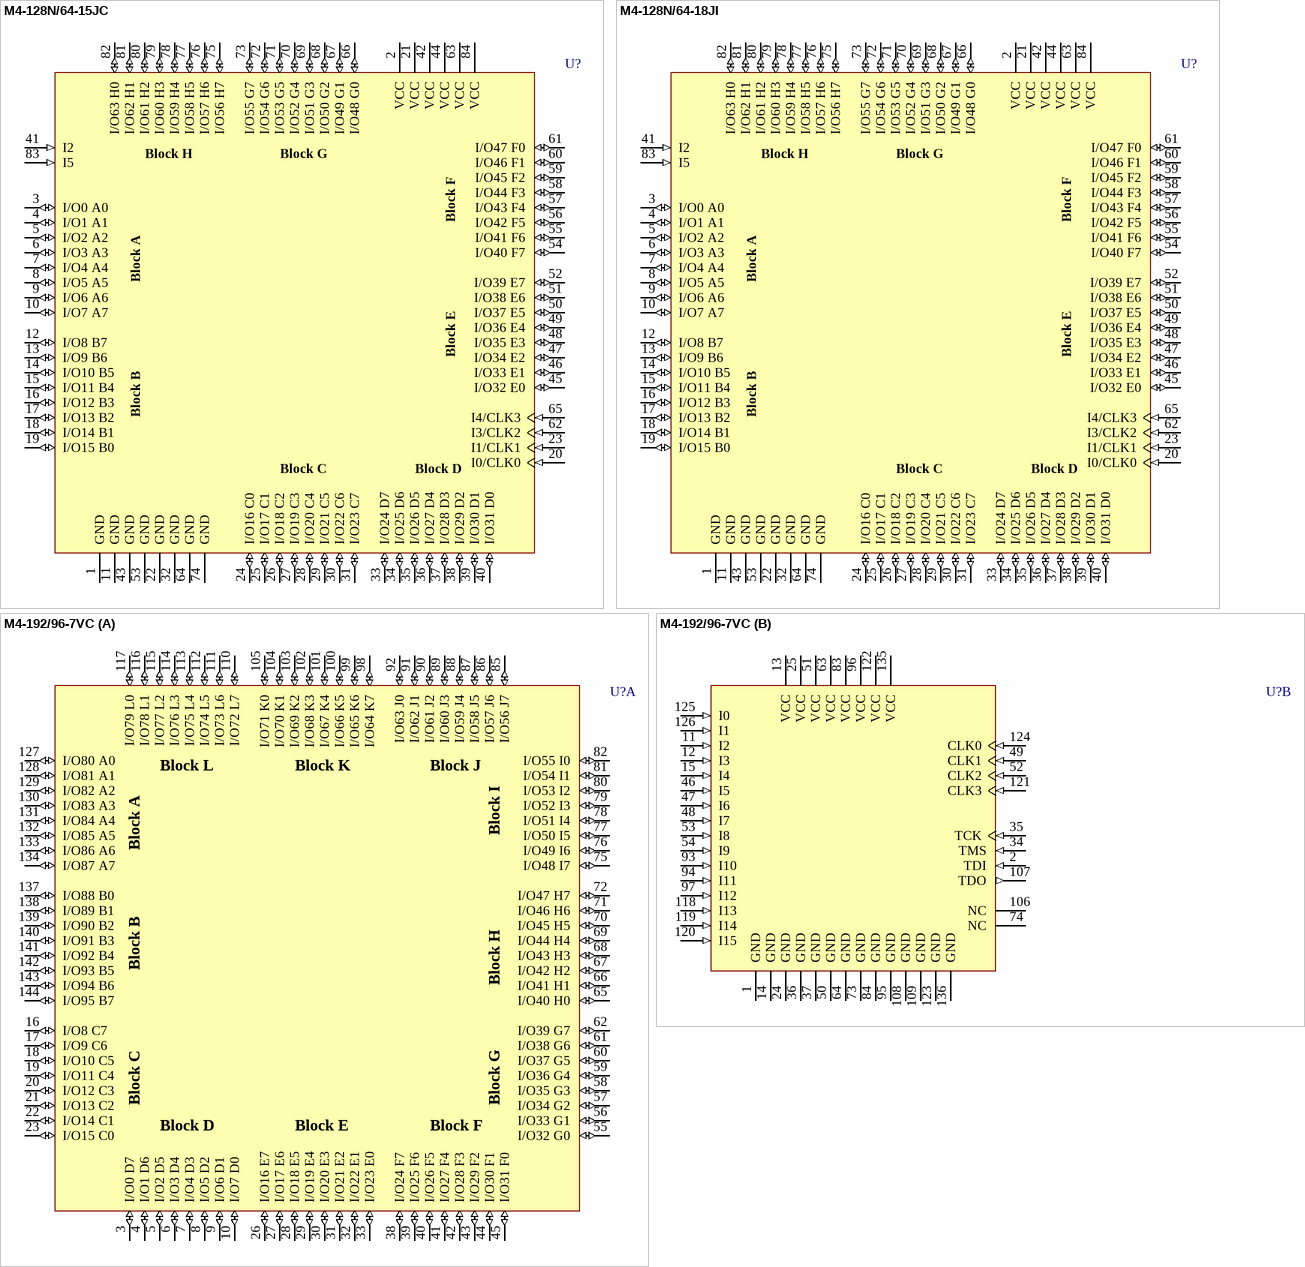
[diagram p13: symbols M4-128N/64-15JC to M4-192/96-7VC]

## M4-128N/64-15JC
designator U?
High-Performance EE CMOS In-System Programmable Logic
footprint PLCC84_N (Leaded Chip Carrier, 84-Leads, Body 29.3x29.3mm, Pitch 1.27mm, IPC Medium Density)
footprint PLCC84_L (Leaded Chip Carrier, 84-Leads, Body 29.3x29.3mm, Pitch 1.27mm, IPC High Density)
footprint PLCC84_M (Leaded Chip Carrier, 84-Leads, Body 29.3x29.3mm, Pitch 1.27mm, IPC Low Density)
3D model M4-PLCC84 (84-Pin Leaded Chip Carrier 1.27 mm Pitch)
pins: 1 GND (power), 2 VCC (power), 3 I/O0 A0 (io), 4 I/O1 A1 (io), 5 I/O2 A2 (io), 6 I/O3 A3 (io), 7 I/O4 A4 (io), 8 I/O5 A5 (io), 9 I/O6 A6 (io), 10 I/O7 A7 (io), 11 GND (power), 12 I/O8 B7 (io), 13 I/O9 B6 (io), 14 I/O10 B5 (io), 15 I/O11 B4 (io), 16 I/O12 B3 (io), 17 I/O13 B2 (io), 18 I/O14 B1 (io), 19 I/O15 B0 (io), 20 I0/CLK0 (in), 21 VCC (power), 22 GND (power), 23 I1/CLK1 (in), 24 I/O16 C0 (io), 25 I/O17 C1 (io), 26 I/O18 C2 (io), 27 I/O19 C3 (io), 28 I/O20 C4 (io), 29 I/O21 C5 (io), 30 I/O22 C6 (io), 31 I/O23 C7 (io), 32 GND (power), 33 I/O24 D7 (io), 34 I/O25 D6 (io), 35 I/O26 D5 (io), 36 I/O27 D4 (io), 37 I/O28 D3 (io), 38 I/O29 D2 (io), 39 I/O30 D1 (io), 40 I/O31 D0 (io), 41 I2 (in), 42 VCC (power), 43 GND (power), 44 VCC (power), 45 I/O32 E0 (io), 46 I/O33 E1 (io), 47 I/O34 E2 (io), 48 I/O35 E3 (io), 49 I/O36 E4 (io), 50 I/O37 E5 (io), 51 I/O38 E6 (io), 52 I/O39 E7 (io), 53 GND (power), 54 I/O40 F7 (io), 55 I/O41 F6 (io), 56 I/O42 F5 (io), 57 I/O43 F4 (io), 58 I/O44 F3 (io), 59 I/O45 F2 (io), 60 I/O46 F1 (io), 61 I/O47 F0 (io), 62 I3/CLK2 (in), 63 VCC (power), 64 GND (power), 65 I4/CLK3 (in), 66 I/O48 G0 (io), 67 I/O49 G1 (io), 68 I/O50 G2 (io), 69 I/O51 G3 (io), 70 I/O52 G4 (io), 71 I/O53 G5 (io), 72 I/O54 G6 (io), 73 I/O55 G7 (io), 74 GND (power), 75 I/O56 H7 (io), 76 I/O57 H6 (io), 77 I/O58 H5 (io), 78 I/O59 H4 (io), 79 I/O60 H3 (io), 80 I/O61 H2 (io), 81 I/O62 H1 (io), 82 I/O63 H0 (io), 83 I5 (in), 84 VCC (power)

## M4-128N/64-18JI
designator U?
High-Performance EE CMOS In-System Programmable Logic
footprint PLCC84_N (Leaded Chip Carrier, 84-Leads, Body 29.3x29.3mm, Pitch 1.27mm, IPC Medium Density)
footprint PLCC84_L (Leaded Chip Carrier, 84-Leads, Body 29.3x29.3mm, Pitch 1.27mm, IPC High Density)
footprint PLCC84_M (Leaded Chip Carrier, 84-Leads, Body 29.3x29.3mm, Pitch 1.27mm, IPC Low Density)
3D model M4-PLCC84 (84-Pin Leaded Chip Carrier 1.27 mm Pitch)
pins: 1 GND (power), 2 VCC (power), 3 I/O0 A0 (io), 4 I/O1 A1 (io), 5 I/O2 A2 (io), 6 I/O3 A3 (io), 7 I/O4 A4 (io), 8 I/O5 A5 (io), 9 I/O6 A6 (io), 10 I/O7 A7 (io), 11 GND (power), 12 I/O8 B7 (io), 13 I/O9 B6 (io), 14 I/O10 B5 (io), 15 I/O11 B4 (io), 16 I/O12 B3 (io), 17 I/O13 B2 (io), 18 I/O14 B1 (io), 19 I/O15 B0 (io), 20 I0/CLK0 (in), 21 VCC (power), 22 GND (power), 23 I1/CLK1 (in), 24 I/O16 C0 (io), 25 I/O17 C1 (io), 26 I/O18 C2 (io), 27 I/O19 C3 (io), 28 I/O20 C4 (io), 29 I/O21 C5 (io), 30 I/O22 C6 (io), 31 I/O23 C7 (io), 32 GND (power), 33 I/O24 D7 (io), 34 I/O25 D6 (io), 35 I/O26 D5 (io), 36 I/O27 D4 (io), 37 I/O28 D3 (io), 38 I/O29 D2 (io), 39 I/O30 D1 (io), 40 I/O31 D0 (io), 41 I2 (in), 42 VCC (power), 43 GND (power), 44 VCC (power), 45 I/O32 E0 (io), 46 I/O33 E1 (io), 47 I/O34 E2 (io), 48 I/O35 E3 (io), 49 I/O36 E4 (io), 50 I/O37 E5 (io), 51 I/O38 E6 (io), 52 I/O39 E7 (io), 53 GND (power), 54 I/O40 F7 (io), 55 I/O41 F6 (io), 56 I/O42 F5 (io), 57 I/O43 F4 (io), 58 I/O44 F3 (io), 59 I/O45 F2 (io), 60 I/O46 F1 (io), 61 I/O47 F0 (io), 62 I3/CLK2 (in), 63 VCC (power), 64 GND (power), 65 I4/CLK3 (in), 66 I/O48 G0 (io), 67 I/O49 G1 (io), 68 I/O50 G2 (io), 69 I/O51 G3 (io), 70 I/O52 G4 (io), 71 I/O53 G5 (io), 72 I/O54 G6 (io), 73 I/O55 G7 (io), 74 GND (power), 75 I/O56 H7 (io), 76 I/O57 H6 (io), 77 I/O58 H5 (io), 78 I/O59 H4 (io), 79 I/O60 H3 (io), 80 I/O61 H2 (io), 81 I/O62 H1 (io), 82 I/O63 H0 (io), 83 I5 (in), 84 VCC (power)

## M4-192/96-7VC
designator U?
High-Performance EE CMOS In-System Programmable Logic
footprint TQFP144_N (Thin QFP, 144-Leads, Body 20x20mm, Pitch 0.5mm, IPC Medium Density)
footprint TQFP144_L (Thin QFP, 144-Leads, Body 20x20mm, Pitch 0.5mm, IPC High Density)
footprint TQFP144_M (Thin QFP, 144-Leads, Body 20x20mm, Pitch 0.5mm, IPC Low Density)
3D model M4-TQFP144 (144-Pin Thin Quad Flat Pack (TQFP144))
part A pins: 3 I/O0 D7 (io), 4 I/O1 D6 (io), 5 I/O2 D5 (io), 6 I/O3 D4 (io), 7 I/O4 D3 (io), 8 I/O5 D2 (io), 9 I/O6 D1 (io), 10 I/O7 D0 (io), 16 I/O8 C7 (io), 17 I/O9 C6 (io), 18 I/O10 C5 (io), 19 I/O11 C4 (io), 20 I/O12 C3 (io), 21 I/O13 C2 (io), 22 I/O14 C1 (io), 23 I/O15 C0 (io), 26 I/O16 E7 (io), 27 I/O17 E6 (io), 28 I/O18 E5 (io), 29 I/O19 E4 (io), 30 I/O20 E3 (io), 31 I/O21 E2 (io), 32 I/O22 E1 (io), 33 I/O23 E0 (io), 38 I/O24 F7 (io), 39 I/O25 F6 (io), 40 I/O26 F5 (io), 41 I/O27 F4 (io), 42 I/O28 F3 (io), 43 I/O29 F2 (io), 44 I/O30 F1 (io), 45 I/O31 F0 (io), 55 I/O32 G0 (io), 56 I/O33 G1 (io), 57 I/O34 G2 (io), 58 I/O35 G3 (io), 59 I/O36 G4 (io), 60 I/O37 G5 (io), 61 I/O38 G6 (io), 62 I/O39 G7 (io), 65 I/O40 H0 (io), 66 I/O41 H1 (io), 67 I/O42 H2 (io), 68 I/O43 H3 (io), 69 I/O44 H4 (io), 70 I/O45 H5 (io), 71 I/O46 H6 (io), 72 I/O47 H7 (io), 75 I/O48 I7 (io), 76 I/O49 I6 (io), 77 I/O50 I5 (io), 78 I/O51 I4 (io), 79 I/O52 I3 (io), 80 I/O53 I2 (io), 81 I/O54 I1 (io), 82 I/O55 I0 (io), 85 I/O56 J7 (io), 86 I/O57 J6 (io), 87 I/O58 J5 (io), 88 I/O59 J4 (io), 89 I/O60 J3 (io), 90 I/O61 J2 (io), 91 I/O62 J1 (io), 92 I/O63 J0 (io), 98 I/O64 K7 (io), 99 I/O65 K6 (io), 100 I/O66 K5 (io), 101 I/O67 K4 (io), 102 I/O68 K3 (io), 103 I/O69 K2 (io), 104 I/O70 K1 (io), 105 I/O71 K0 (io), 110 I/O72 L7 (io), 111 I/O73 L6 (io), 112 I/O74 L5 (io), 113 I/O75 L4 (io), 114 I/O76 L3 (io), 115 I/O77 L2 (io), 116 I/O78 L1 (io), 117 I/O79 L0 (io), 127 I/O80 A0 (io), 128 I/O81 A1 (io), 129 I/O82 A2 (io), 130 I/O83 A3 (io), 131 I/O84 A4 (io), 132 I/O85 A5 (io), 133 I/O86 A6 (io), 134 I/O87 A7 (io), 137 I/O88 B0 (io), 138 I/O89 B1 (io), 139 I/O90 B2 (io), 140 I/O91 B3 (io), 141 I/O92 B4 (io), 142 I/O93 B5 (io), 143 I/O94 B6 (io), 144 I/O95 B7 (io)
part B pins: 1 GND (power), 2 TDI (in), 11 I2 (in), 12 I3 (in), 13 VCC (power), 14 GND (power), 15 I4 (in), 24 GND (power), 25 VCC (power), 34 TMS (in), 35 TCK (in), 36 GND (power), 37 GND (power), 46 I5 (in), 47 I6 (in), 48 I7 (in), 49 CLK1 (in), 50 GND (power), 51 VCC (power), 52 CLK2 (in), 53 I8 (in), 54 I9 (in), 63 VCC (power), 64 GND (power), 73 GND (power), 74 NC, 83 VCC (power), 84 GND (power), 93 I10 (in), 94 I11 (in), 95 GND (power), 96 VCC (power), 97 I12 (in), 106 NC, 107 TDO (out), 108 GND (power), 109 GND (power), 118 I13 (in), 119 I14 (in), 120 I15 (in), 121 CLK3 (in), 122 VCC (power), 123 GND (power), 124 CLK0 (in), 125 I0 (in), 126 I1 (in), 135 VCC (power), 136 GND (power)

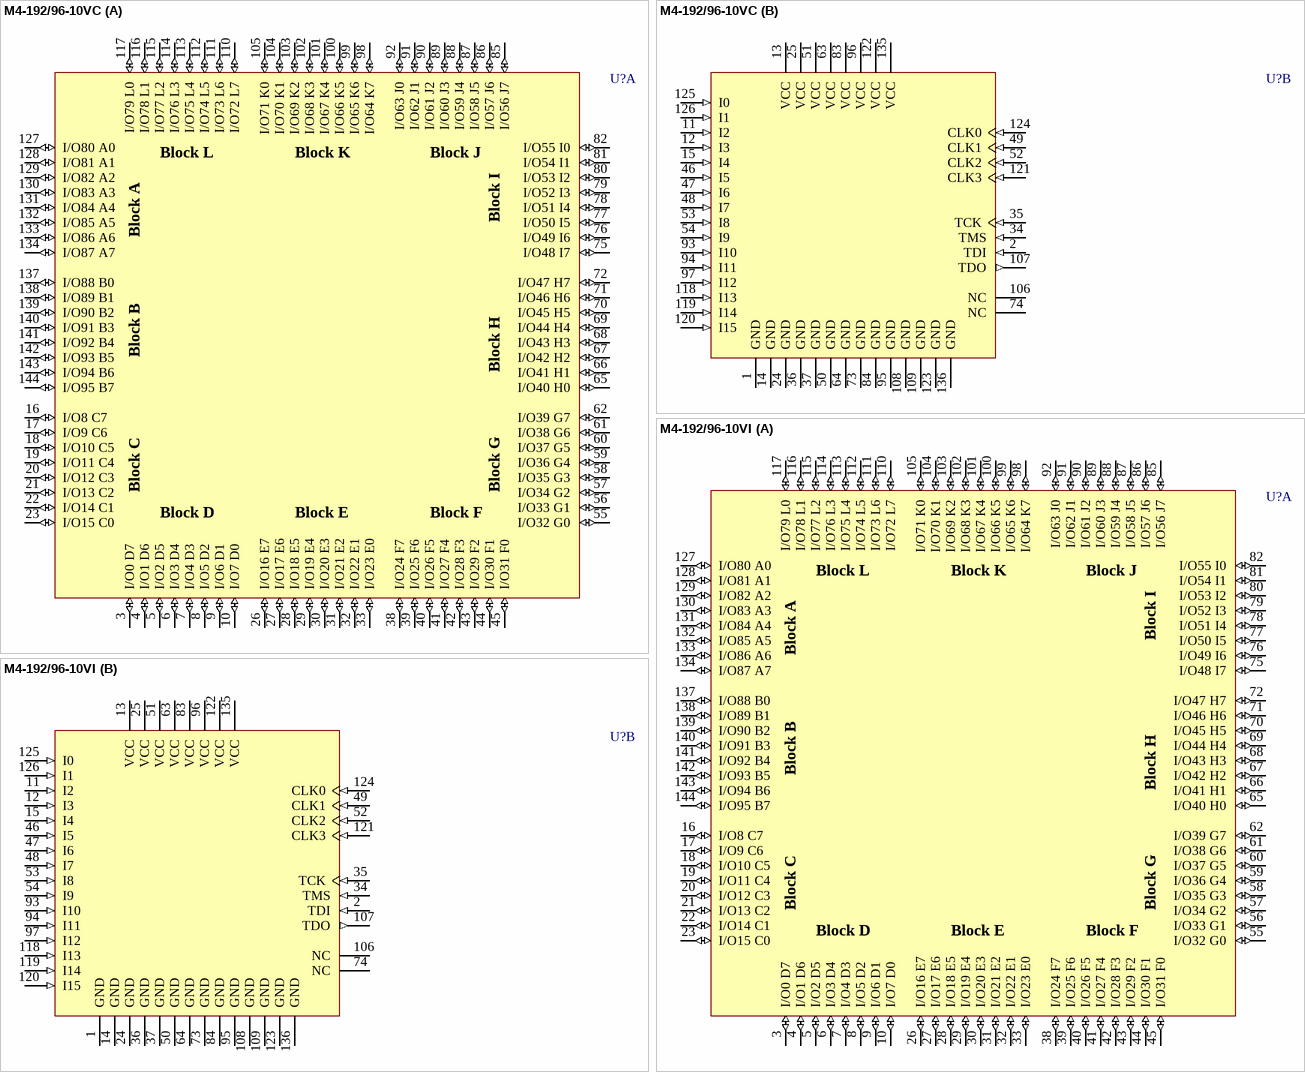
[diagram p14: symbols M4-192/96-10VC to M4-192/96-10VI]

## M4-192/96-10VC
designator U?
High-Performance EE CMOS In-System Programmable Logic
footprint TQFP144_N (Thin QFP, 144-Leads, Body 20x20mm, Pitch 0.5mm, IPC Medium Density)
footprint TQFP144_L (Thin QFP, 144-Leads, Body 20x20mm, Pitch 0.5mm, IPC High Density)
footprint TQFP144_M (Thin QFP, 144-Leads, Body 20x20mm, Pitch 0.5mm, IPC Low Density)
3D model M4-TQFP144 (144-Pin Thin Quad Flat Pack (TQFP144))
part A pins: 3 I/O0 D7 (io), 4 I/O1 D6 (io), 5 I/O2 D5 (io), 6 I/O3 D4 (io), 7 I/O4 D3 (io), 8 I/O5 D2 (io), 9 I/O6 D1 (io), 10 I/O7 D0 (io), 16 I/O8 C7 (io), 17 I/O9 C6 (io), 18 I/O10 C5 (io), 19 I/O11 C4 (io), 20 I/O12 C3 (io), 21 I/O13 C2 (io), 22 I/O14 C1 (io), 23 I/O15 C0 (io), 26 I/O16 E7 (io), 27 I/O17 E6 (io), 28 I/O18 E5 (io), 29 I/O19 E4 (io), 30 I/O20 E3 (io), 31 I/O21 E2 (io), 32 I/O22 E1 (io), 33 I/O23 E0 (io), 38 I/O24 F7 (io), 39 I/O25 F6 (io), 40 I/O26 F5 (io), 41 I/O27 F4 (io), 42 I/O28 F3 (io), 43 I/O29 F2 (io), 44 I/O30 F1 (io), 45 I/O31 F0 (io), 55 I/O32 G0 (io), 56 I/O33 G1 (io), 57 I/O34 G2 (io), 58 I/O35 G3 (io), 59 I/O36 G4 (io), 60 I/O37 G5 (io), 61 I/O38 G6 (io), 62 I/O39 G7 (io), 65 I/O40 H0 (io), 66 I/O41 H1 (io), 67 I/O42 H2 (io), 68 I/O43 H3 (io), 69 I/O44 H4 (io), 70 I/O45 H5 (io), 71 I/O46 H6 (io), 72 I/O47 H7 (io), 75 I/O48 I7 (io), 76 I/O49 I6 (io), 77 I/O50 I5 (io), 78 I/O51 I4 (io), 79 I/O52 I3 (io), 80 I/O53 I2 (io), 81 I/O54 I1 (io), 82 I/O55 I0 (io), 85 I/O56 J7 (io), 86 I/O57 J6 (io), 87 I/O58 J5 (io), 88 I/O59 J4 (io), 89 I/O60 J3 (io), 90 I/O61 J2 (io), 91 I/O62 J1 (io), 92 I/O63 J0 (io), 98 I/O64 K7 (io), 99 I/O65 K6 (io), 100 I/O66 K5 (io), 101 I/O67 K4 (io), 102 I/O68 K3 (io), 103 I/O69 K2 (io), 104 I/O70 K1 (io), 105 I/O71 K0 (io), 110 I/O72 L7 (io), 111 I/O73 L6 (io), 112 I/O74 L5 (io), 113 I/O75 L4 (io), 114 I/O76 L3 (io), 115 I/O77 L2 (io), 116 I/O78 L1 (io), 117 I/O79 L0 (io), 127 I/O80 A0 (io), 128 I/O81 A1 (io), 129 I/O82 A2 (io), 130 I/O83 A3 (io), 131 I/O84 A4 (io), 132 I/O85 A5 (io), 133 I/O86 A6 (io), 134 I/O87 A7 (io), 137 I/O88 B0 (io), 138 I/O89 B1 (io), 139 I/O90 B2 (io), 140 I/O91 B3 (io), 141 I/O92 B4 (io), 142 I/O93 B5 (io), 143 I/O94 B6 (io), 144 I/O95 B7 (io)
part B pins: 1 GND (power), 2 TDI (in), 11 I2 (in), 12 I3 (in), 13 VCC (power), 14 GND (power), 15 I4 (in), 24 GND (power), 25 VCC (power), 34 TMS (in), 35 TCK (in), 36 GND (power), 37 GND (power), 46 I5 (in), 47 I6 (in), 48 I7 (in), 49 CLK1 (in), 50 GND (power), 51 VCC (power), 52 CLK2 (in), 53 I8 (in), 54 I9 (in), 63 VCC (power), 64 GND (power), 73 GND (power), 74 NC, 83 VCC (power), 84 GND (power), 93 I10 (in), 94 I11 (in), 95 GND (power), 96 VCC (power), 97 I12 (in), 106 NC, 107 TDO (out), 108 GND (power), 109 GND (power), 118 I13 (in), 119 I14 (in), 120 I15 (in), 121 CLK3 (in), 122 VCC (power), 123 GND (power), 124 CLK0 (in), 125 I0 (in), 126 I1 (in), 135 VCC (power), 136 GND (power)

## M4-192/96-10VI
designator U?
High-Performance EE CMOS In-System Programmable Logic
footprint TQFP144_N (Thin QFP, 144-Leads, Body 20x20mm, Pitch 0.5mm, IPC Medium Density)
footprint TQFP144_L (Thin QFP, 144-Leads, Body 20x20mm, Pitch 0.5mm, IPC High Density)
footprint TQFP144_M (Thin QFP, 144-Leads, Body 20x20mm, Pitch 0.5mm, IPC Low Density)
3D model M4-TQFP144 (144-Pin Thin Quad Flat Pack (TQFP144))
part A pins: 3 I/O0 D7 (io), 4 I/O1 D6 (io), 5 I/O2 D5 (io), 6 I/O3 D4 (io), 7 I/O4 D3 (io), 8 I/O5 D2 (io), 9 I/O6 D1 (io), 10 I/O7 D0 (io), 16 I/O8 C7 (io), 17 I/O9 C6 (io), 18 I/O10 C5 (io), 19 I/O11 C4 (io), 20 I/O12 C3 (io), 21 I/O13 C2 (io), 22 I/O14 C1 (io), 23 I/O15 C0 (io), 26 I/O16 E7 (io), 27 I/O17 E6 (io), 28 I/O18 E5 (io), 29 I/O19 E4 (io), 30 I/O20 E3 (io), 31 I/O21 E2 (io), 32 I/O22 E1 (io), 33 I/O23 E0 (io), 38 I/O24 F7 (io), 39 I/O25 F6 (io), 40 I/O26 F5 (io), 41 I/O27 F4 (io), 42 I/O28 F3 (io), 43 I/O29 F2 (io), 44 I/O30 F1 (io), 45 I/O31 F0 (io), 55 I/O32 G0 (io), 56 I/O33 G1 (io), 57 I/O34 G2 (io), 58 I/O35 G3 (io), 59 I/O36 G4 (io), 60 I/O37 G5 (io), 61 I/O38 G6 (io), 62 I/O39 G7 (io), 65 I/O40 H0 (io), 66 I/O41 H1 (io), 67 I/O42 H2 (io), 68 I/O43 H3 (io), 69 I/O44 H4 (io), 70 I/O45 H5 (io), 71 I/O46 H6 (io), 72 I/O47 H7 (io), 75 I/O48 I7 (io), 76 I/O49 I6 (io), 77 I/O50 I5 (io), 78 I/O51 I4 (io), 79 I/O52 I3 (io), 80 I/O53 I2 (io), 81 I/O54 I1 (io), 82 I/O55 I0 (io), 85 I/O56 J7 (io), 86 I/O57 J6 (io), 87 I/O58 J5 (io), 88 I/O59 J4 (io), 89 I/O60 J3 (io), 90 I/O61 J2 (io), 91 I/O62 J1 (io), 92 I/O63 J0 (io), 98 I/O64 K7 (io), 99 I/O65 K6 (io), 100 I/O66 K5 (io), 101 I/O67 K4 (io), 102 I/O68 K3 (io), 103 I/O69 K2 (io), 104 I/O70 K1 (io), 105 I/O71 K0 (io), 110 I/O72 L7 (io), 111 I/O73 L6 (io), 112 I/O74 L5 (io), 113 I/O75 L4 (io), 114 I/O76 L3 (io), 115 I/O77 L2 (io), 116 I/O78 L1 (io), 117 I/O79 L0 (io), 127 I/O80 A0 (io), 128 I/O81 A1 (io), 129 I/O82 A2 (io), 130 I/O83 A3 (io), 131 I/O84 A4 (io), 132 I/O85 A5 (io), 133 I/O86 A6 (io), 134 I/O87 A7 (io), 137 I/O88 B0 (io), 138 I/O89 B1 (io), 139 I/O90 B2 (io), 140 I/O91 B3 (io), 141 I/O92 B4 (io), 142 I/O93 B5 (io), 143 I/O94 B6 (io), 144 I/O95 B7 (io)
part B pins: 1 GND (power), 2 TDI (in), 11 I2 (in), 12 I3 (in), 13 VCC (power), 14 GND (power), 15 I4 (in), 24 GND (power), 25 VCC (power), 34 TMS (in), 35 TCK (in), 36 GND (power), 37 GND (power), 46 I5 (in), 47 I6 (in), 48 I7 (in), 49 CLK1 (in), 50 GND (power), 51 VCC (power), 52 CLK2 (in), 53 I8 (in), 54 I9 (in), 63 VCC (power), 64 GND (power), 73 GND (power), 74 NC, 83 VCC (power), 84 GND (power), 93 I10 (in), 94 I11 (in), 95 GND (power), 96 VCC (power), 97 I12 (in), 106 NC, 107 TDO (out), 108 GND (power), 109 GND (power), 118 I13 (in), 119 I14 (in), 120 I15 (in), 121 CLK3 (in), 122 VCC (power), 123 GND (power), 124 CLK0 (in), 125 I0 (in), 126 I1 (in), 135 VCC (power), 136 GND (power)

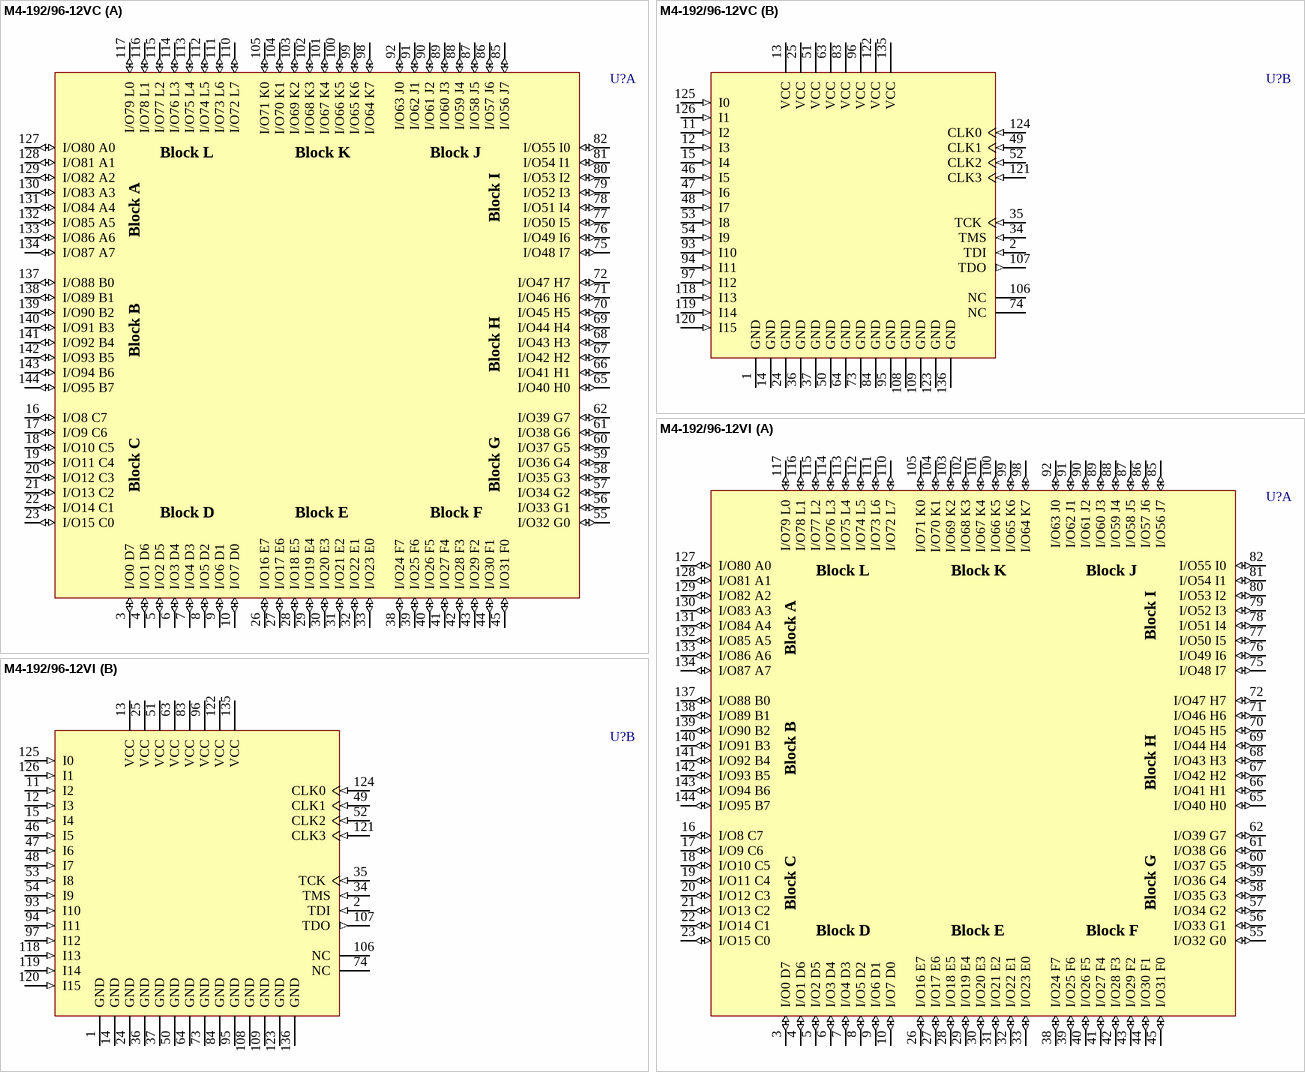
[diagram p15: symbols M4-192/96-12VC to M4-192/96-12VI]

## M4-192/96-12VC
designator U?
High-Performance EE CMOS In-System Programmable Logic
footprint TQFP144_N (Thin QFP, 144-Leads, Body 20x20mm, Pitch 0.5mm, IPC Medium Density)
footprint TQFP144_L (Thin QFP, 144-Leads, Body 20x20mm, Pitch 0.5mm, IPC High Density)
footprint TQFP144_M (Thin QFP, 144-Leads, Body 20x20mm, Pitch 0.5mm, IPC Low Density)
3D model M4-TQFP144 (144-Pin Thin Quad Flat Pack (TQFP144))
part A pins: 3 I/O0 D7 (io), 4 I/O1 D6 (io), 5 I/O2 D5 (io), 6 I/O3 D4 (io), 7 I/O4 D3 (io), 8 I/O5 D2 (io), 9 I/O6 D1 (io), 10 I/O7 D0 (io), 16 I/O8 C7 (io), 17 I/O9 C6 (io), 18 I/O10 C5 (io), 19 I/O11 C4 (io), 20 I/O12 C3 (io), 21 I/O13 C2 (io), 22 I/O14 C1 (io), 23 I/O15 C0 (io), 26 I/O16 E7 (io), 27 I/O17 E6 (io), 28 I/O18 E5 (io), 29 I/O19 E4 (io), 30 I/O20 E3 (io), 31 I/O21 E2 (io), 32 I/O22 E1 (io), 33 I/O23 E0 (io), 38 I/O24 F7 (io), 39 I/O25 F6 (io), 40 I/O26 F5 (io), 41 I/O27 F4 (io), 42 I/O28 F3 (io), 43 I/O29 F2 (io), 44 I/O30 F1 (io), 45 I/O31 F0 (io), 55 I/O32 G0 (io), 56 I/O33 G1 (io), 57 I/O34 G2 (io), 58 I/O35 G3 (io), 59 I/O36 G4 (io), 60 I/O37 G5 (io), 61 I/O38 G6 (io), 62 I/O39 G7 (io), 65 I/O40 H0 (io), 66 I/O41 H1 (io), 67 I/O42 H2 (io), 68 I/O43 H3 (io), 69 I/O44 H4 (io), 70 I/O45 H5 (io), 71 I/O46 H6 (io), 72 I/O47 H7 (io), 75 I/O48 I7 (io), 76 I/O49 I6 (io), 77 I/O50 I5 (io), 78 I/O51 I4 (io), 79 I/O52 I3 (io), 80 I/O53 I2 (io), 81 I/O54 I1 (io), 82 I/O55 I0 (io), 85 I/O56 J7 (io), 86 I/O57 J6 (io), 87 I/O58 J5 (io), 88 I/O59 J4 (io), 89 I/O60 J3 (io), 90 I/O61 J2 (io), 91 I/O62 J1 (io), 92 I/O63 J0 (io), 98 I/O64 K7 (io), 99 I/O65 K6 (io), 100 I/O66 K5 (io), 101 I/O67 K4 (io), 102 I/O68 K3 (io), 103 I/O69 K2 (io), 104 I/O70 K1 (io), 105 I/O71 K0 (io), 110 I/O72 L7 (io), 111 I/O73 L6 (io), 112 I/O74 L5 (io), 113 I/O75 L4 (io), 114 I/O76 L3 (io), 115 I/O77 L2 (io), 116 I/O78 L1 (io), 117 I/O79 L0 (io), 127 I/O80 A0 (io), 128 I/O81 A1 (io), 129 I/O82 A2 (io), 130 I/O83 A3 (io), 131 I/O84 A4 (io), 132 I/O85 A5 (io), 133 I/O86 A6 (io), 134 I/O87 A7 (io), 137 I/O88 B0 (io), 138 I/O89 B1 (io), 139 I/O90 B2 (io), 140 I/O91 B3 (io), 141 I/O92 B4 (io), 142 I/O93 B5 (io), 143 I/O94 B6 (io), 144 I/O95 B7 (io)
part B pins: 1 GND (power), 2 TDI (in), 11 I2 (in), 12 I3 (in), 13 VCC (power), 14 GND (power), 15 I4 (in), 24 GND (power), 25 VCC (power), 34 TMS (in), 35 TCK (in), 36 GND (power), 37 GND (power), 46 I5 (in), 47 I6 (in), 48 I7 (in), 49 CLK1 (in), 50 GND (power), 51 VCC (power), 52 CLK2 (in), 53 I8 (in), 54 I9 (in), 63 VCC (power), 64 GND (power), 73 GND (power), 74 NC, 83 VCC (power), 84 GND (power), 93 I10 (in), 94 I11 (in), 95 GND (power), 96 VCC (power), 97 I12 (in), 106 NC, 107 TDO (out), 108 GND (power), 109 GND (power), 118 I13 (in), 119 I14 (in), 120 I15 (in), 121 CLK3 (in), 122 VCC (power), 123 GND (power), 124 CLK0 (in), 125 I0 (in), 126 I1 (in), 135 VCC (power), 136 GND (power)

## M4-192/96-12VI
designator U?
High-Performance EE CMOS In-System Programmable Logic
footprint TQFP144_N (Thin QFP, 144-Leads, Body 20x20mm, Pitch 0.5mm, IPC Medium Density)
footprint TQFP144_L (Thin QFP, 144-Leads, Body 20x20mm, Pitch 0.5mm, IPC High Density)
footprint TQFP144_M (Thin QFP, 144-Leads, Body 20x20mm, Pitch 0.5mm, IPC Low Density)
3D model M4-TQFP144 (144-Pin Thin Quad Flat Pack (TQFP144))
part A pins: 3 I/O0 D7 (io), 4 I/O1 D6 (io), 5 I/O2 D5 (io), 6 I/O3 D4 (io), 7 I/O4 D3 (io), 8 I/O5 D2 (io), 9 I/O6 D1 (io), 10 I/O7 D0 (io), 16 I/O8 C7 (io), 17 I/O9 C6 (io), 18 I/O10 C5 (io), 19 I/O11 C4 (io), 20 I/O12 C3 (io), 21 I/O13 C2 (io), 22 I/O14 C1 (io), 23 I/O15 C0 (io), 26 I/O16 E7 (io), 27 I/O17 E6 (io), 28 I/O18 E5 (io), 29 I/O19 E4 (io), 30 I/O20 E3 (io), 31 I/O21 E2 (io), 32 I/O22 E1 (io), 33 I/O23 E0 (io), 38 I/O24 F7 (io), 39 I/O25 F6 (io), 40 I/O26 F5 (io), 41 I/O27 F4 (io), 42 I/O28 F3 (io), 43 I/O29 F2 (io), 44 I/O30 F1 (io), 45 I/O31 F0 (io), 55 I/O32 G0 (io), 56 I/O33 G1 (io), 57 I/O34 G2 (io), 58 I/O35 G3 (io), 59 I/O36 G4 (io), 60 I/O37 G5 (io), 61 I/O38 G6 (io), 62 I/O39 G7 (io), 65 I/O40 H0 (io), 66 I/O41 H1 (io), 67 I/O42 H2 (io), 68 I/O43 H3 (io), 69 I/O44 H4 (io), 70 I/O45 H5 (io), 71 I/O46 H6 (io), 72 I/O47 H7 (io), 75 I/O48 I7 (io), 76 I/O49 I6 (io), 77 I/O50 I5 (io), 78 I/O51 I4 (io), 79 I/O52 I3 (io), 80 I/O53 I2 (io), 81 I/O54 I1 (io), 82 I/O55 I0 (io), 85 I/O56 J7 (io), 86 I/O57 J6 (io), 87 I/O58 J5 (io), 88 I/O59 J4 (io), 89 I/O60 J3 (io), 90 I/O61 J2 (io), 91 I/O62 J1 (io), 92 I/O63 J0 (io), 98 I/O64 K7 (io), 99 I/O65 K6 (io), 100 I/O66 K5 (io), 101 I/O67 K4 (io), 102 I/O68 K3 (io), 103 I/O69 K2 (io), 104 I/O70 K1 (io), 105 I/O71 K0 (io), 110 I/O72 L7 (io), 111 I/O73 L6 (io), 112 I/O74 L5 (io), 113 I/O75 L4 (io), 114 I/O76 L3 (io), 115 I/O77 L2 (io), 116 I/O78 L1 (io), 117 I/O79 L0 (io), 127 I/O80 A0 (io), 128 I/O81 A1 (io), 129 I/O82 A2 (io), 130 I/O83 A3 (io), 131 I/O84 A4 (io), 132 I/O85 A5 (io), 133 I/O86 A6 (io), 134 I/O87 A7 (io), 137 I/O88 B0 (io), 138 I/O89 B1 (io), 139 I/O90 B2 (io), 140 I/O91 B3 (io), 141 I/O92 B4 (io), 142 I/O93 B5 (io), 143 I/O94 B6 (io), 144 I/O95 B7 (io)
part B pins: 1 GND (power), 2 TDI (in), 11 I2 (in), 12 I3 (in), 13 VCC (power), 14 GND (power), 15 I4 (in), 24 GND (power), 25 VCC (power), 34 TMS (in), 35 TCK (in), 36 GND (power), 37 GND (power), 46 I5 (in), 47 I6 (in), 48 I7 (in), 49 CLK1 (in), 50 GND (power), 51 VCC (power), 52 CLK2 (in), 53 I8 (in), 54 I9 (in), 63 VCC (power), 64 GND (power), 73 GND (power), 74 NC, 83 VCC (power), 84 GND (power), 93 I10 (in), 94 I11 (in), 95 GND (power), 96 VCC (power), 97 I12 (in), 106 NC, 107 TDO (out), 108 GND (power), 109 GND (power), 118 I13 (in), 119 I14 (in), 120 I15 (in), 121 CLK3 (in), 122 VCC (power), 123 GND (power), 124 CLK0 (in), 125 I0 (in), 126 I1 (in), 135 VCC (power), 136 GND (power)

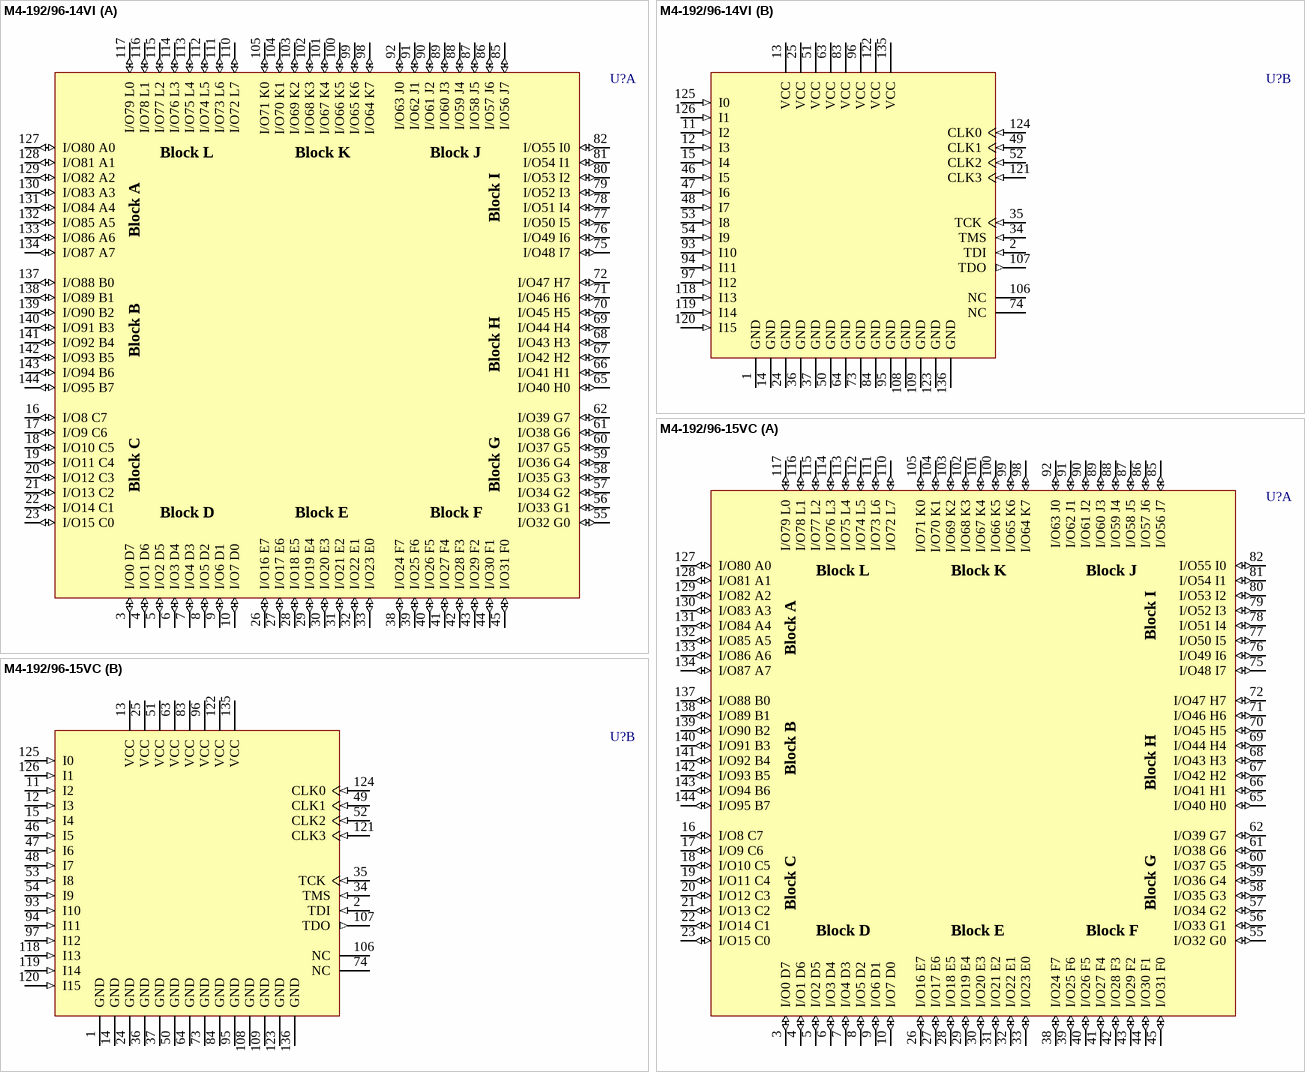
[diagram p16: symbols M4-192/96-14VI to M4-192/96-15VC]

## M4-192/96-14VI
designator U?
High-Performance EE CMOS In-System Programmable Logic
footprint TQFP144_N (Thin QFP, 144-Leads, Body 20x20mm, Pitch 0.5mm, IPC Medium Density)
footprint TQFP144_L (Thin QFP, 144-Leads, Body 20x20mm, Pitch 0.5mm, IPC High Density)
footprint TQFP144_M (Thin QFP, 144-Leads, Body 20x20mm, Pitch 0.5mm, IPC Low Density)
3D model M4-TQFP144 (144-Pin Thin Quad Flat Pack (TQFP144))
part A pins: 3 I/O0 D7 (io), 4 I/O1 D6 (io), 5 I/O2 D5 (io), 6 I/O3 D4 (io), 7 I/O4 D3 (io), 8 I/O5 D2 (io), 9 I/O6 D1 (io), 10 I/O7 D0 (io), 16 I/O8 C7 (io), 17 I/O9 C6 (io), 18 I/O10 C5 (io), 19 I/O11 C4 (io), 20 I/O12 C3 (io), 21 I/O13 C2 (io), 22 I/O14 C1 (io), 23 I/O15 C0 (io), 26 I/O16 E7 (io), 27 I/O17 E6 (io), 28 I/O18 E5 (io), 29 I/O19 E4 (io), 30 I/O20 E3 (io), 31 I/O21 E2 (io), 32 I/O22 E1 (io), 33 I/O23 E0 (io), 38 I/O24 F7 (io), 39 I/O25 F6 (io), 40 I/O26 F5 (io), 41 I/O27 F4 (io), 42 I/O28 F3 (io), 43 I/O29 F2 (io), 44 I/O30 F1 (io), 45 I/O31 F0 (io), 55 I/O32 G0 (io), 56 I/O33 G1 (io), 57 I/O34 G2 (io), 58 I/O35 G3 (io), 59 I/O36 G4 (io), 60 I/O37 G5 (io), 61 I/O38 G6 (io), 62 I/O39 G7 (io), 65 I/O40 H0 (io), 66 I/O41 H1 (io), 67 I/O42 H2 (io), 68 I/O43 H3 (io), 69 I/O44 H4 (io), 70 I/O45 H5 (io), 71 I/O46 H6 (io), 72 I/O47 H7 (io), 75 I/O48 I7 (io), 76 I/O49 I6 (io), 77 I/O50 I5 (io), 78 I/O51 I4 (io), 79 I/O52 I3 (io), 80 I/O53 I2 (io), 81 I/O54 I1 (io), 82 I/O55 I0 (io), 85 I/O56 J7 (io), 86 I/O57 J6 (io), 87 I/O58 J5 (io), 88 I/O59 J4 (io), 89 I/O60 J3 (io), 90 I/O61 J2 (io), 91 I/O62 J1 (io), 92 I/O63 J0 (io), 98 I/O64 K7 (io), 99 I/O65 K6 (io), 100 I/O66 K5 (io), 101 I/O67 K4 (io), 102 I/O68 K3 (io), 103 I/O69 K2 (io), 104 I/O70 K1 (io), 105 I/O71 K0 (io), 110 I/O72 L7 (io), 111 I/O73 L6 (io), 112 I/O74 L5 (io), 113 I/O75 L4 (io), 114 I/O76 L3 (io), 115 I/O77 L2 (io), 116 I/O78 L1 (io), 117 I/O79 L0 (io), 127 I/O80 A0 (io), 128 I/O81 A1 (io), 129 I/O82 A2 (io), 130 I/O83 A3 (io), 131 I/O84 A4 (io), 132 I/O85 A5 (io), 133 I/O86 A6 (io), 134 I/O87 A7 (io), 137 I/O88 B0 (io), 138 I/O89 B1 (io), 139 I/O90 B2 (io), 140 I/O91 B3 (io), 141 I/O92 B4 (io), 142 I/O93 B5 (io), 143 I/O94 B6 (io), 144 I/O95 B7 (io)
part B pins: 1 GND (power), 2 TDI (in), 11 I2 (in), 12 I3 (in), 13 VCC (power), 14 GND (power), 15 I4 (in), 24 GND (power), 25 VCC (power), 34 TMS (in), 35 TCK (in), 36 GND (power), 37 GND (power), 46 I5 (in), 47 I6 (in), 48 I7 (in), 49 CLK1 (in), 50 GND (power), 51 VCC (power), 52 CLK2 (in), 53 I8 (in), 54 I9 (in), 63 VCC (power), 64 GND (power), 73 GND (power), 74 NC, 83 VCC (power), 84 GND (power), 93 I10 (in), 94 I11 (in), 95 GND (power), 96 VCC (power), 97 I12 (in), 106 NC, 107 TDO (out), 108 GND (power), 109 GND (power), 118 I13 (in), 119 I14 (in), 120 I15 (in), 121 CLK3 (in), 122 VCC (power), 123 GND (power), 124 CLK0 (in), 125 I0 (in), 126 I1 (in), 135 VCC (power), 136 GND (power)

## M4-192/96-15VC
designator U?
High-Performance EE CMOS In-System Programmable Logic
footprint TQFP144_N (Thin QFP, 144-Leads, Body 20x20mm, Pitch 0.5mm, IPC Medium Density)
footprint TQFP144_L (Thin QFP, 144-Leads, Body 20x20mm, Pitch 0.5mm, IPC High Density)
footprint TQFP144_M (Thin QFP, 144-Leads, Body 20x20mm, Pitch 0.5mm, IPC Low Density)
3D model M4-TQFP144 (144-Pin Thin Quad Flat Pack (TQFP144))
part A pins: 3 I/O0 D7 (io), 4 I/O1 D6 (io), 5 I/O2 D5 (io), 6 I/O3 D4 (io), 7 I/O4 D3 (io), 8 I/O5 D2 (io), 9 I/O6 D1 (io), 10 I/O7 D0 (io), 16 I/O8 C7 (io), 17 I/O9 C6 (io), 18 I/O10 C5 (io), 19 I/O11 C4 (io), 20 I/O12 C3 (io), 21 I/O13 C2 (io), 22 I/O14 C1 (io), 23 I/O15 C0 (io), 26 I/O16 E7 (io), 27 I/O17 E6 (io), 28 I/O18 E5 (io), 29 I/O19 E4 (io), 30 I/O20 E3 (io), 31 I/O21 E2 (io), 32 I/O22 E1 (io), 33 I/O23 E0 (io), 38 I/O24 F7 (io), 39 I/O25 F6 (io), 40 I/O26 F5 (io), 41 I/O27 F4 (io), 42 I/O28 F3 (io), 43 I/O29 F2 (io), 44 I/O30 F1 (io), 45 I/O31 F0 (io), 55 I/O32 G0 (io), 56 I/O33 G1 (io), 57 I/O34 G2 (io), 58 I/O35 G3 (io), 59 I/O36 G4 (io), 60 I/O37 G5 (io), 61 I/O38 G6 (io), 62 I/O39 G7 (io), 65 I/O40 H0 (io), 66 I/O41 H1 (io), 67 I/O42 H2 (io), 68 I/O43 H3 (io), 69 I/O44 H4 (io), 70 I/O45 H5 (io), 71 I/O46 H6 (io), 72 I/O47 H7 (io), 75 I/O48 I7 (io), 76 I/O49 I6 (io), 77 I/O50 I5 (io), 78 I/O51 I4 (io), 79 I/O52 I3 (io), 80 I/O53 I2 (io), 81 I/O54 I1 (io), 82 I/O55 I0 (io), 85 I/O56 J7 (io), 86 I/O57 J6 (io), 87 I/O58 J5 (io), 88 I/O59 J4 (io), 89 I/O60 J3 (io), 90 I/O61 J2 (io), 91 I/O62 J1 (io), 92 I/O63 J0 (io), 98 I/O64 K7 (io), 99 I/O65 K6 (io), 100 I/O66 K5 (io), 101 I/O67 K4 (io), 102 I/O68 K3 (io), 103 I/O69 K2 (io), 104 I/O70 K1 (io), 105 I/O71 K0 (io), 110 I/O72 L7 (io), 111 I/O73 L6 (io), 112 I/O74 L5 (io), 113 I/O75 L4 (io), 114 I/O76 L3 (io), 115 I/O77 L2 (io), 116 I/O78 L1 (io), 117 I/O79 L0 (io), 127 I/O80 A0 (io), 128 I/O81 A1 (io), 129 I/O82 A2 (io), 130 I/O83 A3 (io), 131 I/O84 A4 (io), 132 I/O85 A5 (io), 133 I/O86 A6 (io), 134 I/O87 A7 (io), 137 I/O88 B0 (io), 138 I/O89 B1 (io), 139 I/O90 B2 (io), 140 I/O91 B3 (io), 141 I/O92 B4 (io), 142 I/O93 B5 (io), 143 I/O94 B6 (io), 144 I/O95 B7 (io)
part B pins: 1 GND (power), 2 TDI (in), 11 I2 (in), 12 I3 (in), 13 VCC (power), 14 GND (power), 15 I4 (in), 24 GND (power), 25 VCC (power), 34 TMS (in), 35 TCK (in), 36 GND (power), 37 GND (power), 46 I5 (in), 47 I6 (in), 48 I7 (in), 49 CLK1 (in), 50 GND (power), 51 VCC (power), 52 CLK2 (in), 53 I8 (in), 54 I9 (in), 63 VCC (power), 64 GND (power), 73 GND (power), 74 NC, 83 VCC (power), 84 GND (power), 93 I10 (in), 94 I11 (in), 95 GND (power), 96 VCC (power), 97 I12 (in), 106 NC, 107 TDO (out), 108 GND (power), 109 GND (power), 118 I13 (in), 119 I14 (in), 120 I15 (in), 121 CLK3 (in), 122 VCC (power), 123 GND (power), 124 CLK0 (in), 125 I0 (in), 126 I1 (in), 135 VCC (power), 136 GND (power)

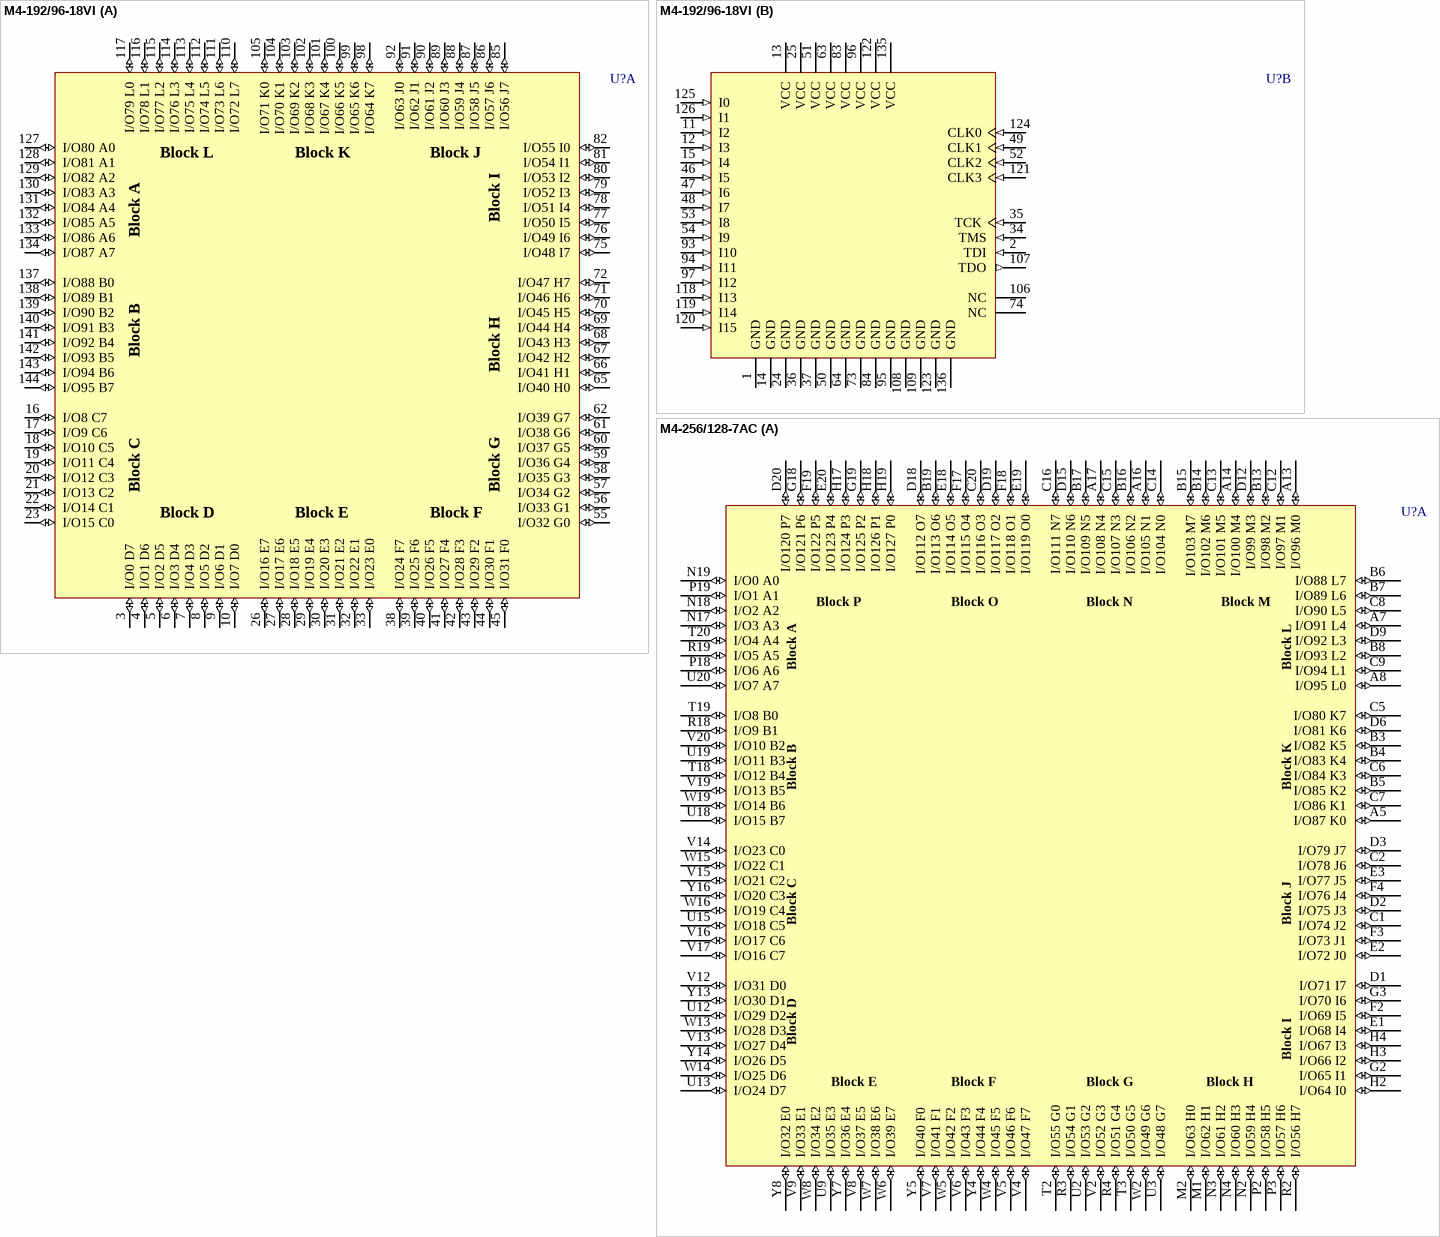
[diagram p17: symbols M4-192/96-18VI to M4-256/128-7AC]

## M4-192/96-18VI
designator U?
High-Performance EE CMOS In-System Programmable Logic
footprint TQFP144_N (Thin QFP, 144-Leads, Body 20x20mm, Pitch 0.5mm, IPC Medium Density)
footprint TQFP144_L (Thin QFP, 144-Leads, Body 20x20mm, Pitch 0.5mm, IPC High Density)
footprint TQFP144_M (Thin QFP, 144-Leads, Body 20x20mm, Pitch 0.5mm, IPC Low Density)
3D model M4-TQFP144 (144-Pin Thin Quad Flat Pack (TQFP144))
part A pins: 3 I/O0 D7 (io), 4 I/O1 D6 (io), 5 I/O2 D5 (io), 6 I/O3 D4 (io), 7 I/O4 D3 (io), 8 I/O5 D2 (io), 9 I/O6 D1 (io), 10 I/O7 D0 (io), 16 I/O8 C7 (io), 17 I/O9 C6 (io), 18 I/O10 C5 (io), 19 I/O11 C4 (io), 20 I/O12 C3 (io), 21 I/O13 C2 (io), 22 I/O14 C1 (io), 23 I/O15 C0 (io), 26 I/O16 E7 (io), 27 I/O17 E6 (io), 28 I/O18 E5 (io), 29 I/O19 E4 (io), 30 I/O20 E3 (io), 31 I/O21 E2 (io), 32 I/O22 E1 (io), 33 I/O23 E0 (io), 38 I/O24 F7 (io), 39 I/O25 F6 (io), 40 I/O26 F5 (io), 41 I/O27 F4 (io), 42 I/O28 F3 (io), 43 I/O29 F2 (io), 44 I/O30 F1 (io), 45 I/O31 F0 (io), 55 I/O32 G0 (io), 56 I/O33 G1 (io), 57 I/O34 G2 (io), 58 I/O35 G3 (io), 59 I/O36 G4 (io), 60 I/O37 G5 (io), 61 I/O38 G6 (io), 62 I/O39 G7 (io), 65 I/O40 H0 (io), 66 I/O41 H1 (io), 67 I/O42 H2 (io), 68 I/O43 H3 (io), 69 I/O44 H4 (io), 70 I/O45 H5 (io), 71 I/O46 H6 (io), 72 I/O47 H7 (io), 75 I/O48 I7 (io), 76 I/O49 I6 (io), 77 I/O50 I5 (io), 78 I/O51 I4 (io), 79 I/O52 I3 (io), 80 I/O53 I2 (io), 81 I/O54 I1 (io), 82 I/O55 I0 (io), 85 I/O56 J7 (io), 86 I/O57 J6 (io), 87 I/O58 J5 (io), 88 I/O59 J4 (io), 89 I/O60 J3 (io), 90 I/O61 J2 (io), 91 I/O62 J1 (io), 92 I/O63 J0 (io), 98 I/O64 K7 (io), 99 I/O65 K6 (io), 100 I/O66 K5 (io), 101 I/O67 K4 (io), 102 I/O68 K3 (io), 103 I/O69 K2 (io), 104 I/O70 K1 (io), 105 I/O71 K0 (io), 110 I/O72 L7 (io), 111 I/O73 L6 (io), 112 I/O74 L5 (io), 113 I/O75 L4 (io), 114 I/O76 L3 (io), 115 I/O77 L2 (io), 116 I/O78 L1 (io), 117 I/O79 L0 (io), 127 I/O80 A0 (io), 128 I/O81 A1 (io), 129 I/O82 A2 (io), 130 I/O83 A3 (io), 131 I/O84 A4 (io), 132 I/O85 A5 (io), 133 I/O86 A6 (io), 134 I/O87 A7 (io), 137 I/O88 B0 (io), 138 I/O89 B1 (io), 139 I/O90 B2 (io), 140 I/O91 B3 (io), 141 I/O92 B4 (io), 142 I/O93 B5 (io), 143 I/O94 B6 (io), 144 I/O95 B7 (io)
part B pins: 1 GND (power), 2 TDI (in), 11 I2 (in), 12 I3 (in), 13 VCC (power), 14 GND (power), 15 I4 (in), 24 GND (power), 25 VCC (power), 34 TMS (in), 35 TCK (in), 36 GND (power), 37 GND (power), 46 I5 (in), 47 I6 (in), 48 I7 (in), 49 CLK1 (in), 50 GND (power), 51 VCC (power), 52 CLK2 (in), 53 I8 (in), 54 I9 (in), 63 VCC (power), 64 GND (power), 73 GND (power), 74 NC, 83 VCC (power), 84 GND (power), 93 I10 (in), 94 I11 (in), 95 GND (power), 96 VCC (power), 97 I12 (in), 106 NC, 107 TDO (out), 108 GND (power), 109 GND (power), 118 I13 (in), 119 I14 (in), 120 I15 (in), 121 CLK3 (in), 122 VCC (power), 123 GND (power), 124 CLK0 (in), 125 I0 (in), 126 I1 (in), 135 VCC (power), 136 GND (power)

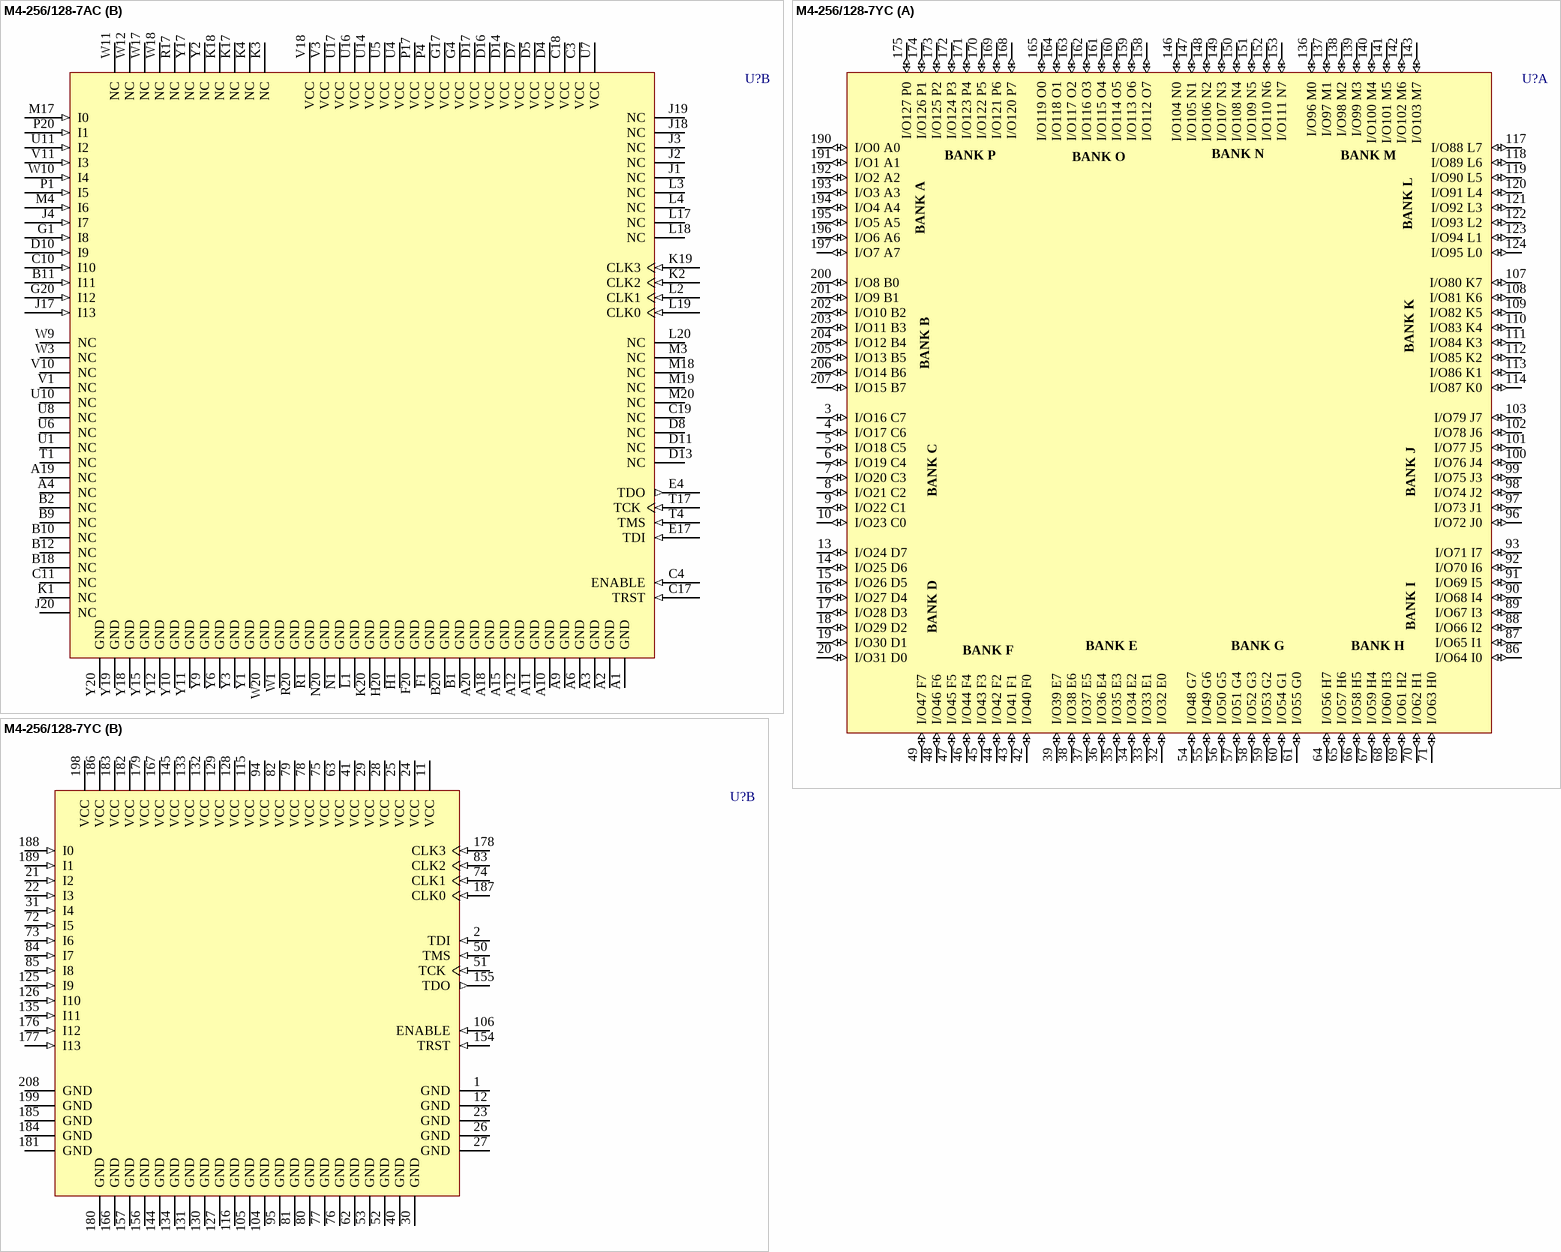
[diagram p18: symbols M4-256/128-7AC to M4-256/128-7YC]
